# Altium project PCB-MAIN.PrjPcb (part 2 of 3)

## Sheet PCB-MAIN_03_AUDIO.SchDoc
size 594 x 420 mm
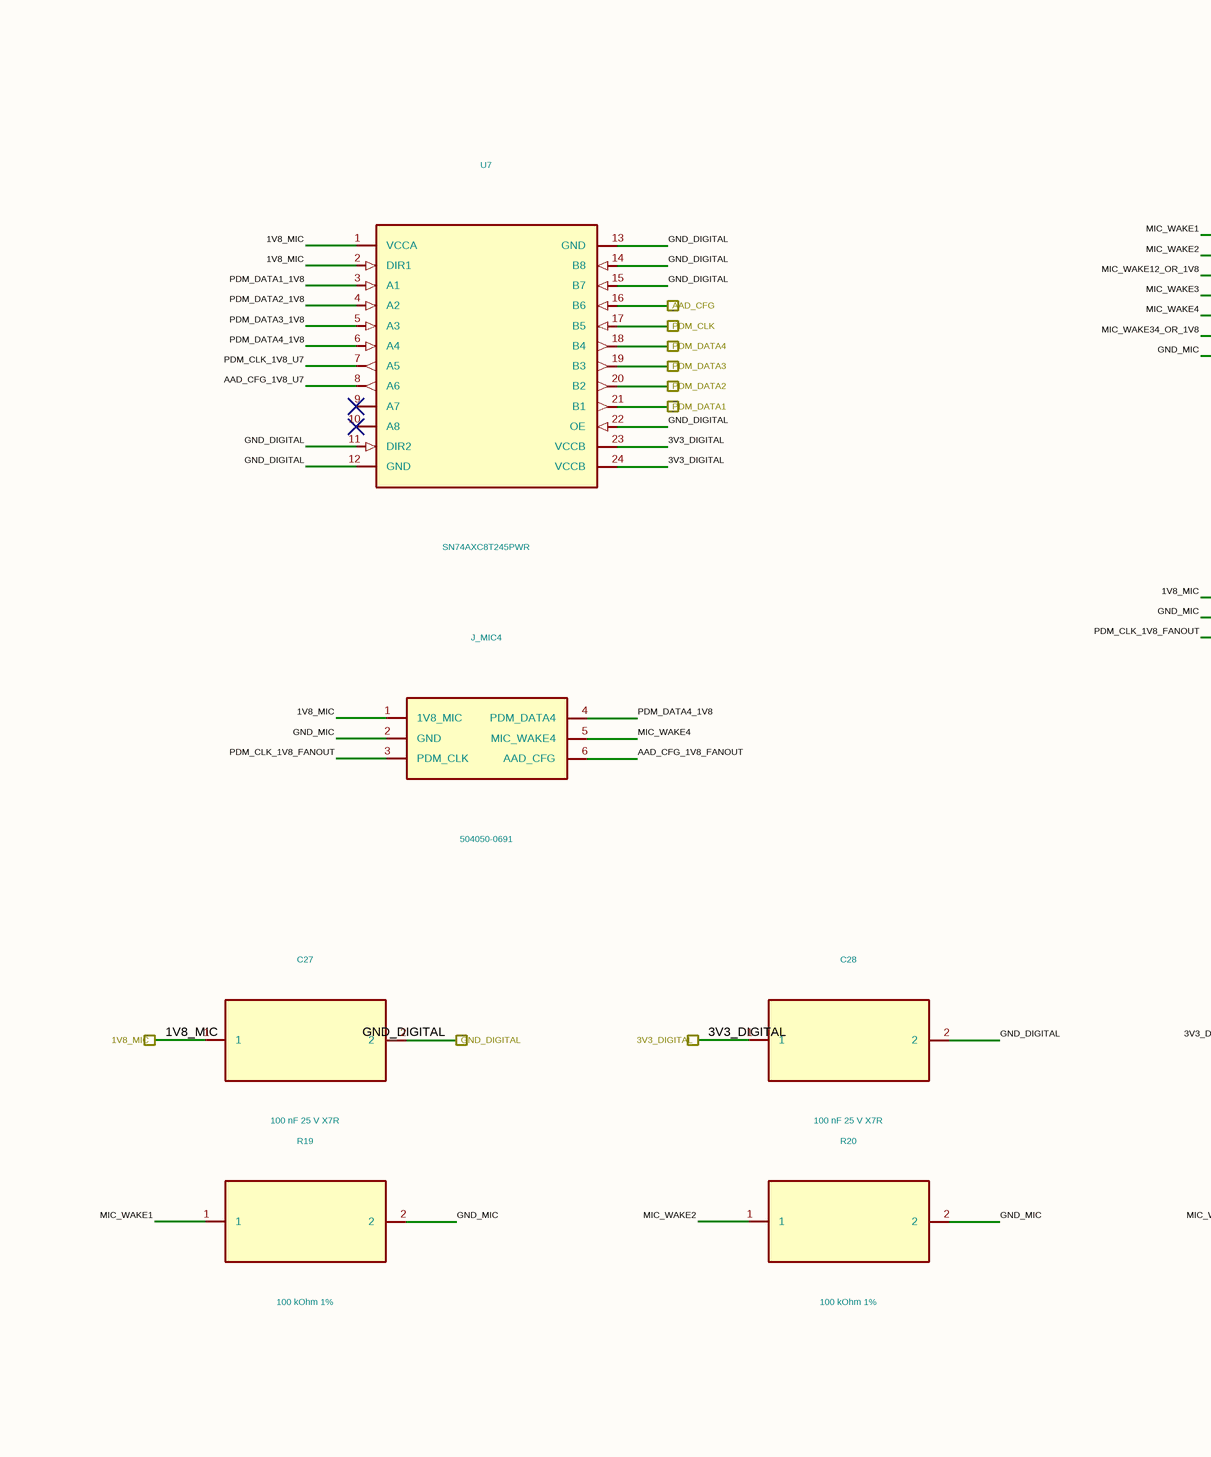
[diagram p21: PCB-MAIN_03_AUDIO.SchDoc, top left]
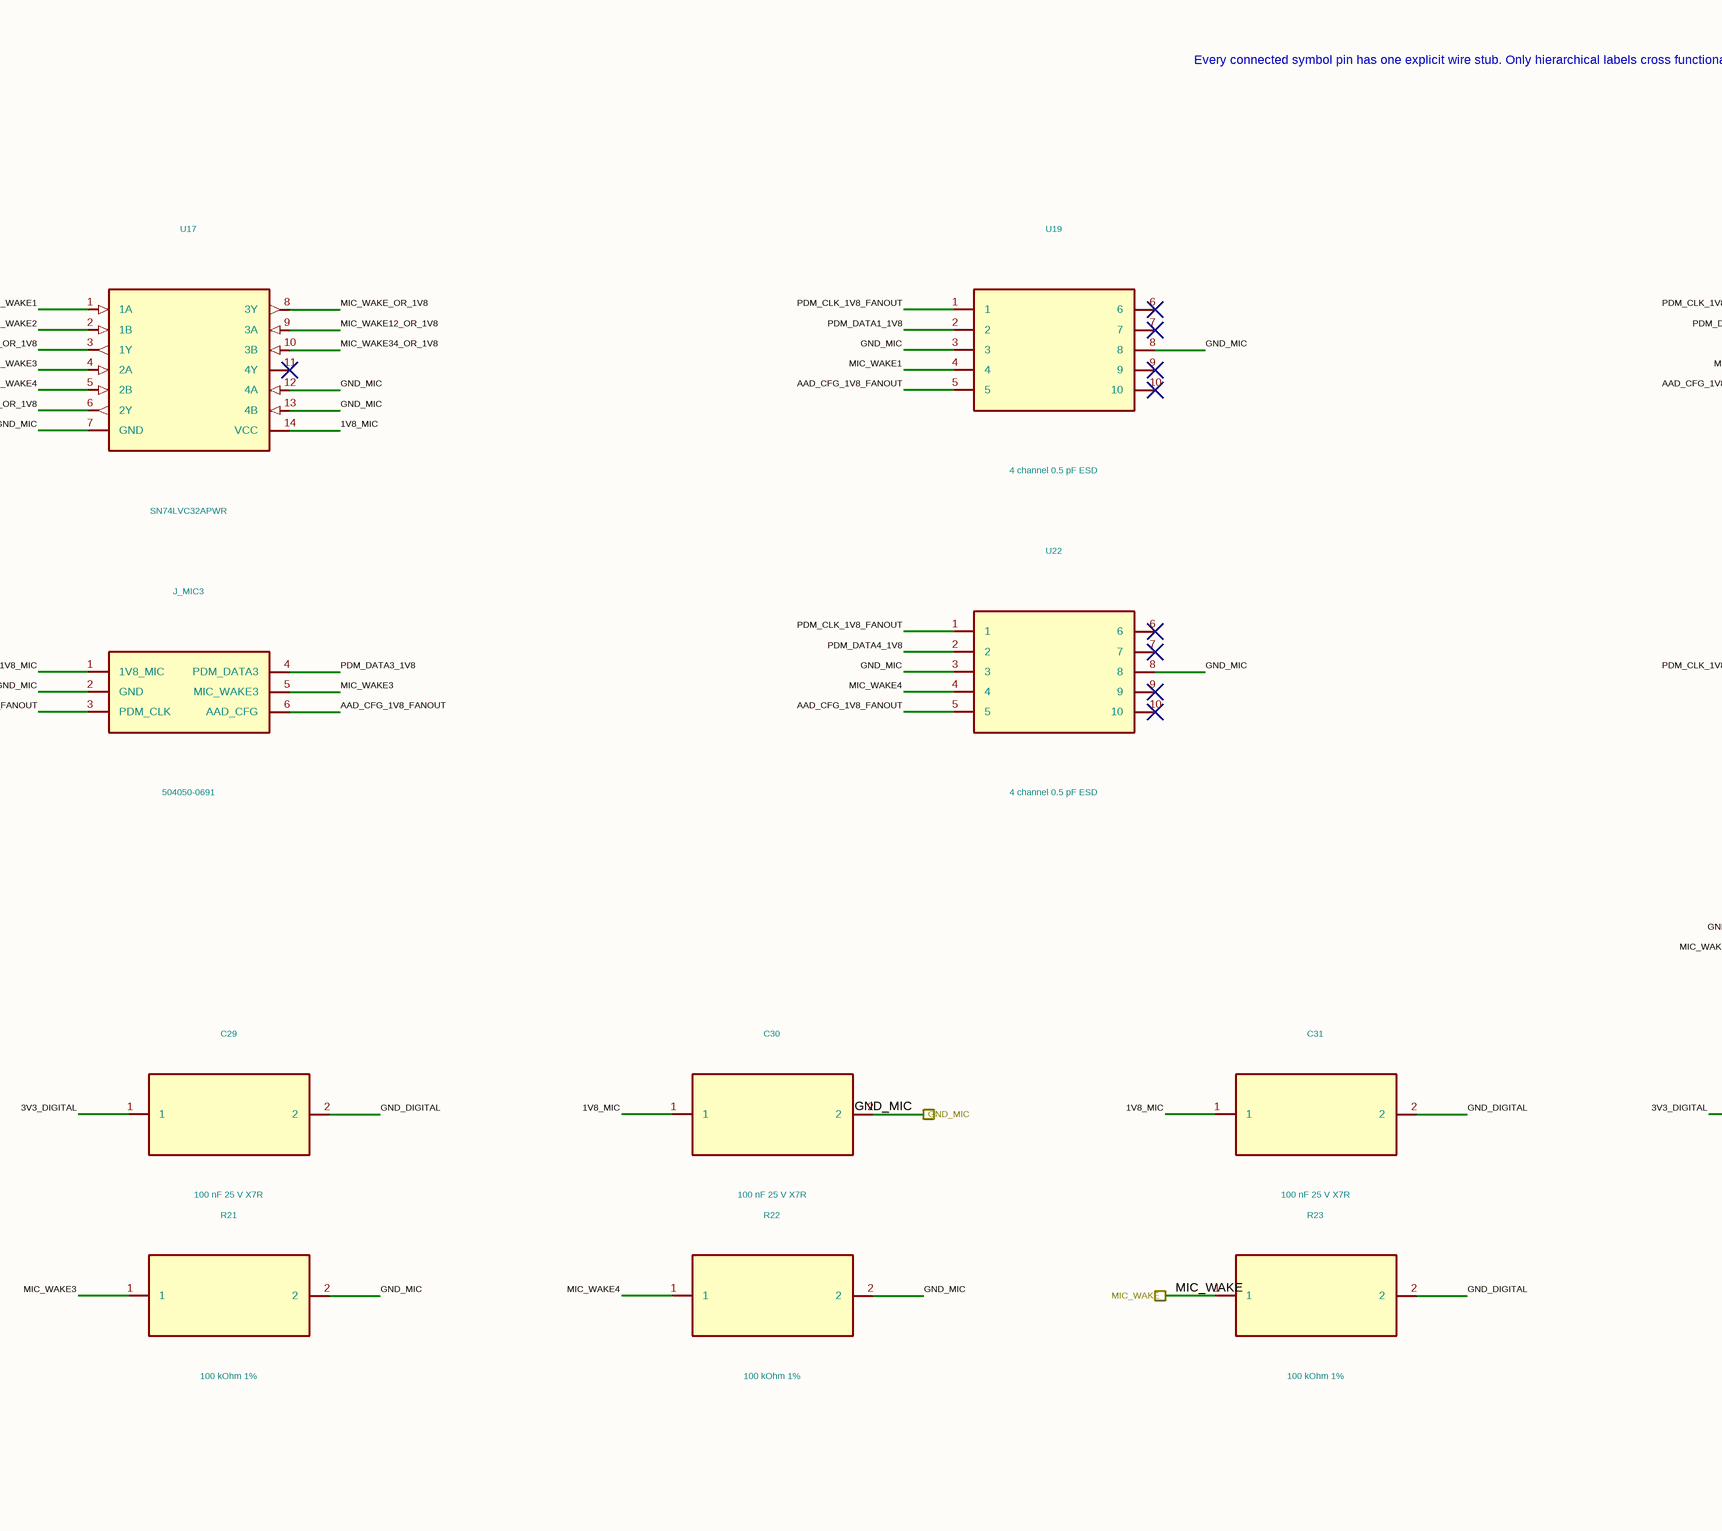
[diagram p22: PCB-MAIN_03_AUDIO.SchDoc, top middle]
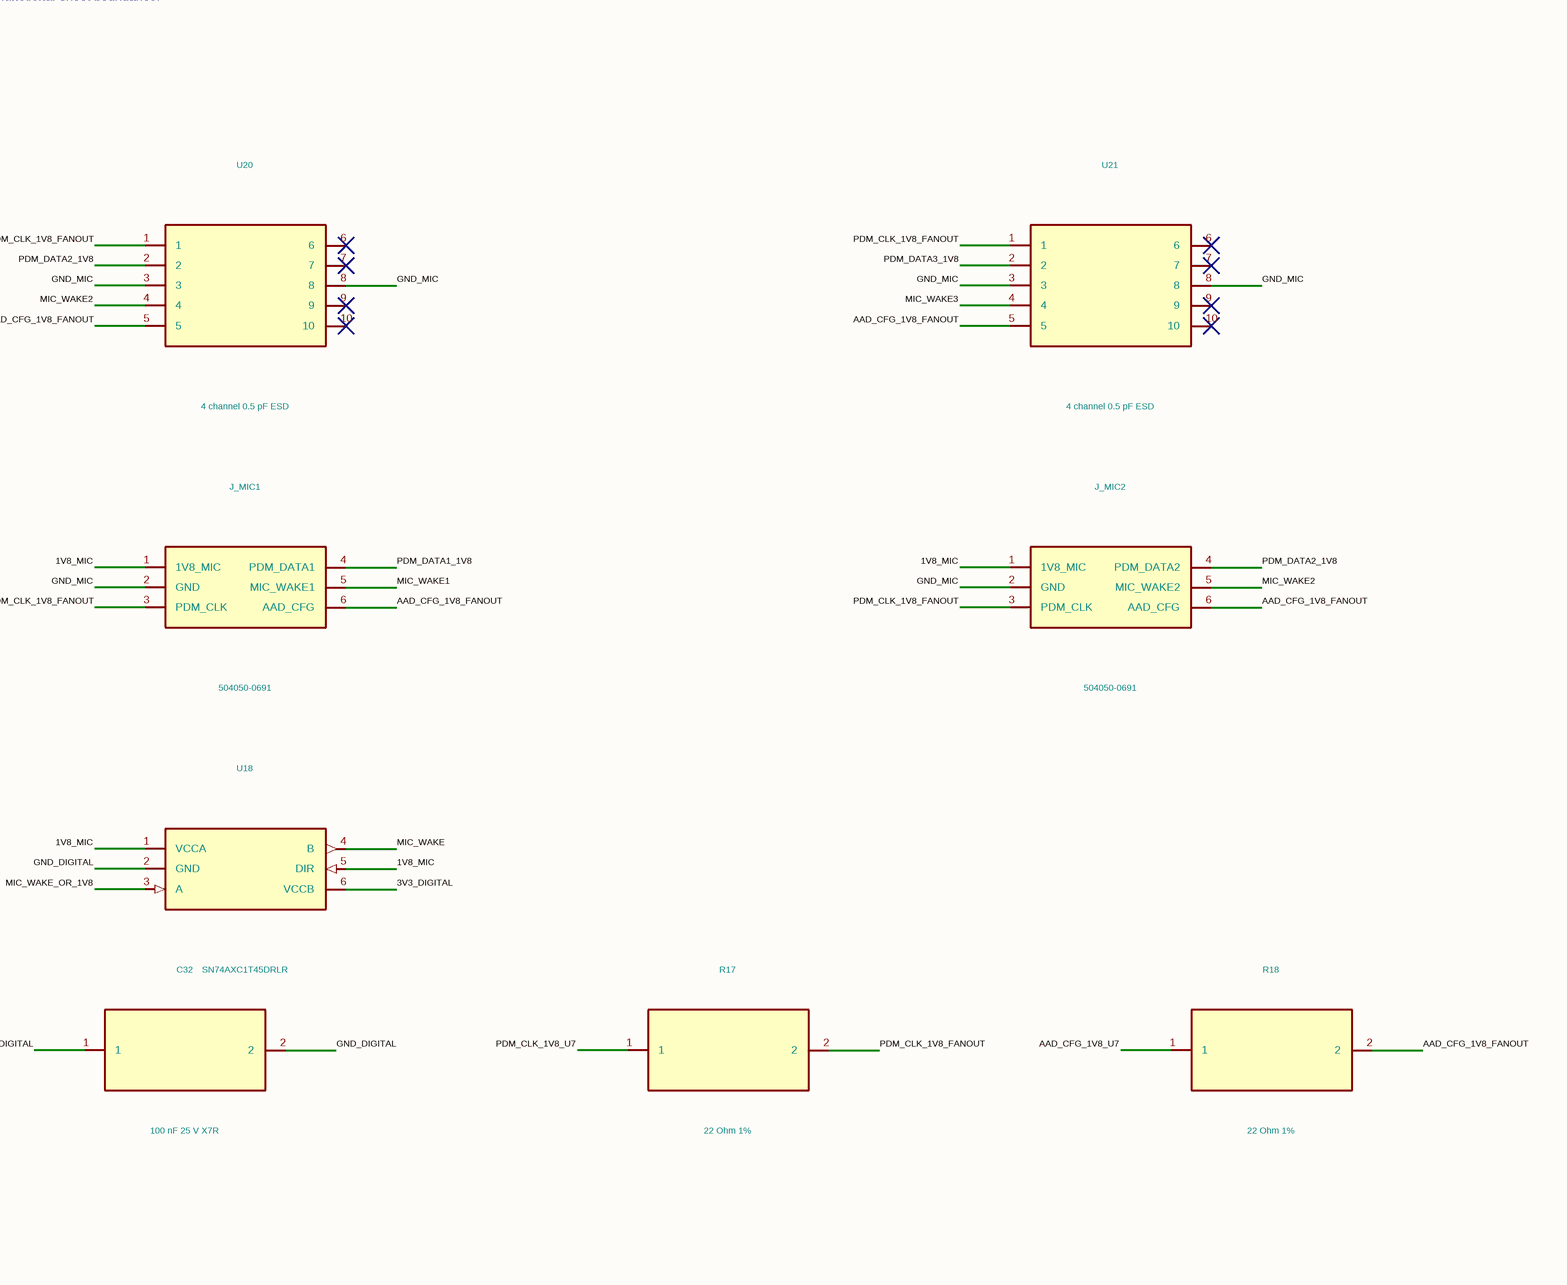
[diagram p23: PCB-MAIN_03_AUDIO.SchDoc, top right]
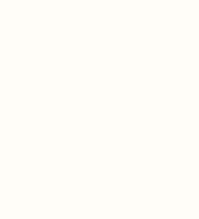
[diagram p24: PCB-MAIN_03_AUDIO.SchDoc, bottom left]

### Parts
C27  100 nF 25 V X7R  [C_0402_1005Metric]
C28  100 nF 25 V X7R  [C_0402_1005Metric]
C29  100 nF 25 V X7R  [C_0402_1005Metric]
C30  100 nF 25 V X7R  [C_0402_1005Metric]
C31  100 nF 25 V X7R  [C_0402_1005Metric]
C32  100 nF 25 V X7R  [C_0402_1005Metric]
J_MIC1  504050-0691
J_MIC2  504050-0691
J_MIC3  504050-0691
J_MIC4  504050-0691
R17  22 Ohm 1%  [R_0402_1005Metric]
R18  22 Ohm 1%  [R_0402_1005Metric]
R19  100 kOhm 1%  [R_0402_1005Metric]
R20  100 kOhm 1%  [R_0402_1005Metric]
R21  100 kOhm 1%  [R_0402_1005Metric]
R22  100 kOhm 1%  [R_0402_1005Metric]
R23  100 kOhm 1%  [R_0402_1005Metric]
U7  SN74AXC8T245PWR
U17  SN74LVC32APWR
U18  SN74AXC1T45DRLR
U19  4 channel 0.5 pF ESD
U20  4 channel 0.5 pF ESD
U21  4 channel 0.5 pF ESD
U22  4 channel 0.5 pF ESD

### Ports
1V8_MIC, 3V3_DIGITAL, AAD_CFG, GND_DIGITAL, GND_MIC, MIC_WAKE, PDM_CLK, PDM_DATA1, PDM_DATA2, PDM_DATA3, PDM_DATA4

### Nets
1V8_MIC: C27.1 C30.1 C31.1 J_MIC1.1(1V8_MIC) J_MIC2.1(1V8_MIC) J_MIC3.1(1V8_MIC) J_MIC4.1(1V8_MIC) U7.1(VCCA) U7.2(DIR1) U17.14(VCC) U18.1(VCCA) U18.5(DIR) ; port 1V8_MIC
3V3_DIGITAL: C28.1 C29.1 C32.1 U7.23(VCCB) U7.24(VCCB) U18.6(VCCB) ; port 3V3_DIGITAL
AAD_CFG: U7.16(B6) ; port AAD_CFG
AAD_CFG_1V8_FANOUT: J_MIC1.6(AAD_CFG) J_MIC2.6(AAD_CFG) J_MIC3.6(AAD_CFG) J_MIC4.6(AAD_CFG) R18.2 U19.5 U20.5 U21.5 U22.5
AAD_CFG_1V8_U7: R18.1 U7.8(A6)
GND_DIGITAL: C27.2 C28.2 C29.2 C31.2 C32.2 R23.2 U7.11(DIR2) U7.12(GND) U7.13(GND) U7.14(B8) U7.15(B7) U7.22(OE) U18.2(GND) ; port GND_DIGITAL
GND_MIC: C30.2 J_MIC1.2(GND) J_MIC2.2(GND) J_MIC3.2(GND) J_MIC4.2(GND) R19.2 R20.2 R21.2 R22.2 U17.7(GND) U17.12(4A) U17.13(4B) U19.3 U19.8 U20.3 U20.8 U21.3 U21.8 U22.3 U22.8 ; port GND_MIC
MIC_WAKE: R23.1 U18.4(B) ; port MIC_WAKE
MIC_WAKE1: J_MIC1.5(MIC_WAKE1) R19.1 U17.1(1A) U19.4
MIC_WAKE2: J_MIC2.5(MIC_WAKE2) R20.1 U17.2(1B) U20.4
MIC_WAKE3: J_MIC3.5(MIC_WAKE3) R21.1 U17.4(2A) U21.4
MIC_WAKE4: J_MIC4.5(MIC_WAKE4) R22.1 U17.5(2B) U22.4
MIC_WAKE12_OR_1V8: U17.3(1Y) U17.9(3A)
MIC_WAKE34_OR_1V8: U17.6(2Y) U17.10(3B)
MIC_WAKE_OR_1V8: U17.8(3Y) U18.3(A)
PDM_CLK: U7.17(B5) ; port PDM_CLK
PDM_CLK_1V8_FANOUT: J_MIC1.3(PDM_CLK) J_MIC2.3(PDM_CLK) J_MIC3.3(PDM_CLK) J_MIC4.3(PDM_CLK) R17.2 U19.1 U20.1 U21.1 U22.1
PDM_CLK_1V8_U7: R17.1 U7.7(A5)
PDM_DATA1: U7.21(B1) ; port PDM_DATA1
PDM_DATA1_1V8: J_MIC1.4(PDM_DATA1) U7.3(A1) U19.2
PDM_DATA2: U7.20(B2) ; port PDM_DATA2
PDM_DATA2_1V8: J_MIC2.4(PDM_DATA2) U7.4(A2) U20.2
PDM_DATA3: U7.19(B3) ; port PDM_DATA3
PDM_DATA3_1V8: J_MIC3.4(PDM_DATA3) U7.5(A3) U21.2
PDM_DATA4: U7.18(B4) ; port PDM_DATA4
PDM_DATA4_1V8: J_MIC4.4(PDM_DATA4) U7.6(A4) U22.2

Not connected (* = marked no-connect by the designer): U7 9(A7)* 10(A8)*; U17 11(4Y)*; U19 6* 7* 9* 10*; U20 6* 7* 9* 10*; U21 6* 7* 9* 10*; U22 6* 7* 9* 10*

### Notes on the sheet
- Every connected symbol pin has one explicit wire stub. Only hierarchical labels cross functional-sheet boundaries.

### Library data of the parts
C27 = C27_GRM155R71E104KE14D: Manufacturer: Murata; Population: FITTED; Authority: TI_SCES875C_RevC
C28 = C28_GRM155R71E104KE14D: Manufacturer: Murata; Population: FITTED; Authority: TI_SCES875C_RevC
C29 = C29_GRM155R71E104KE14D: Manufacturer: Murata; Population: FITTED; Authority: TI_SCES875C_RevC
C30 = C30_GRM155R71E104KE14D: Manufacturer: Murata; Population: FITTED; Authority: TI_SCAS286U_RevU
C31 = C31_GRM155R71E104KE14D: Manufacturer: Murata; Population: FITTED; Authority: TI_SCES882E_RevE
C32 = C32_GRM155R71E104KE14D: Manufacturer: Murata; Population: FITTED; Authority: TI_SCES882E_RevE
J_MIC1 = J_MIC1_504050-0691: Manufacturer: Molex; Population: FITTED; Authority: HARNESS_LOGICAL_PINOUT_REV_A.csv
J_MIC2 = J_MIC2_504050-0691: Manufacturer: Molex; Population: FITTED; Authority: HARNESS_LOGICAL_PINOUT_REV_A.csv
J_MIC3 = J_MIC3_504050-0691: Manufacturer: Molex; Population: FITTED; Authority: HARNESS_LOGICAL_PINOUT_REV_A.csv
J_MIC4 = J_MIC4_504050-0691: Manufacturer: Molex; Population: FITTED; Authority: HARNESS_LOGICAL_PINOUT_REV_A.csv
R17 = R17_ERJ-2RKF22R0X: Manufacturer: Panasonic; Population: FITTED; Authority: PROJECT_MAIN_AUTH_010
R18 = R18_ERJ-2RKF22R0X: Manufacturer: Panasonic; Population: FITTED; Authority: PROJECT_MAIN_AUTH_010
R19 = R19_ERJ-2RKF1003X: Manufacturer: Panasonic; Population: FITTED; Authority: TDK_T5838_DS-000383_Rev1.2
R20 = R20_ERJ-2RKF1003X: Manufacturer: Panasonic; Population: FITTED; Authority: TDK_T5838_DS-000383_Rev1.2
R21 = R21_ERJ-2RKF1003X: Manufacturer: Panasonic; Population: FITTED; Authority: TDK_T5838_DS-000383_Rev1.2
R22 = R22_ERJ-2RKF1003X: Manufacturer: Panasonic; Population: FITTED; Authority: TDK_T5838_DS-000383_Rev1.2
R23 = R23_ERJ-2RKF1003X: Manufacturer: Panasonic; Population: FITTED; Authority: TI_SCES882E_RevE
U7 = U7_SN74AXC8T245PWR: Manufacturer: Texas Instruments; Population: FITTED; Authority: PCB_MAIN_AUDIO_LOGIC_PIN_AUTHORITY_REV_A.csv
U17 = U17_SN74LVC32APWR: Manufacturer: Texas Instruments; Population: FITTED; Authority: PCB_MAIN_AUDIO_LOGIC_PIN_AUTHORITY_REV_A.csv
U18 = U18_SN74AXC1T45DRLR: Manufacturer: Texas Instruments; Population: FITTED; Authority: PCB_MAIN_AUDIO_LOGIC_PIN_AUTHORITY_REV_A.csv
U19 = U19_TPD4E05U06DQAR: Manufacturer: Texas Instruments; Population: FITTED; Authority: TI_TPDxE05U06_RevO
U20 = U20_TPD4E05U06DQAR: Manufacturer: Texas Instruments; Population: FITTED; Authority: TI_TPDxE05U06_RevO
U21 = U21_TPD4E05U06DQAR: Manufacturer: Texas Instruments; Population: FITTED; Authority: TI_TPDxE05U06_RevO
U22 = U22_TPD4E05U06DQAR: Manufacturer: Texas Instruments; Population: FITTED; Authority: TI_TPDxE05U06_RevO

## Sheet PCB-MAIN_04_GNSS.SchDoc
size 594 x 420 mm
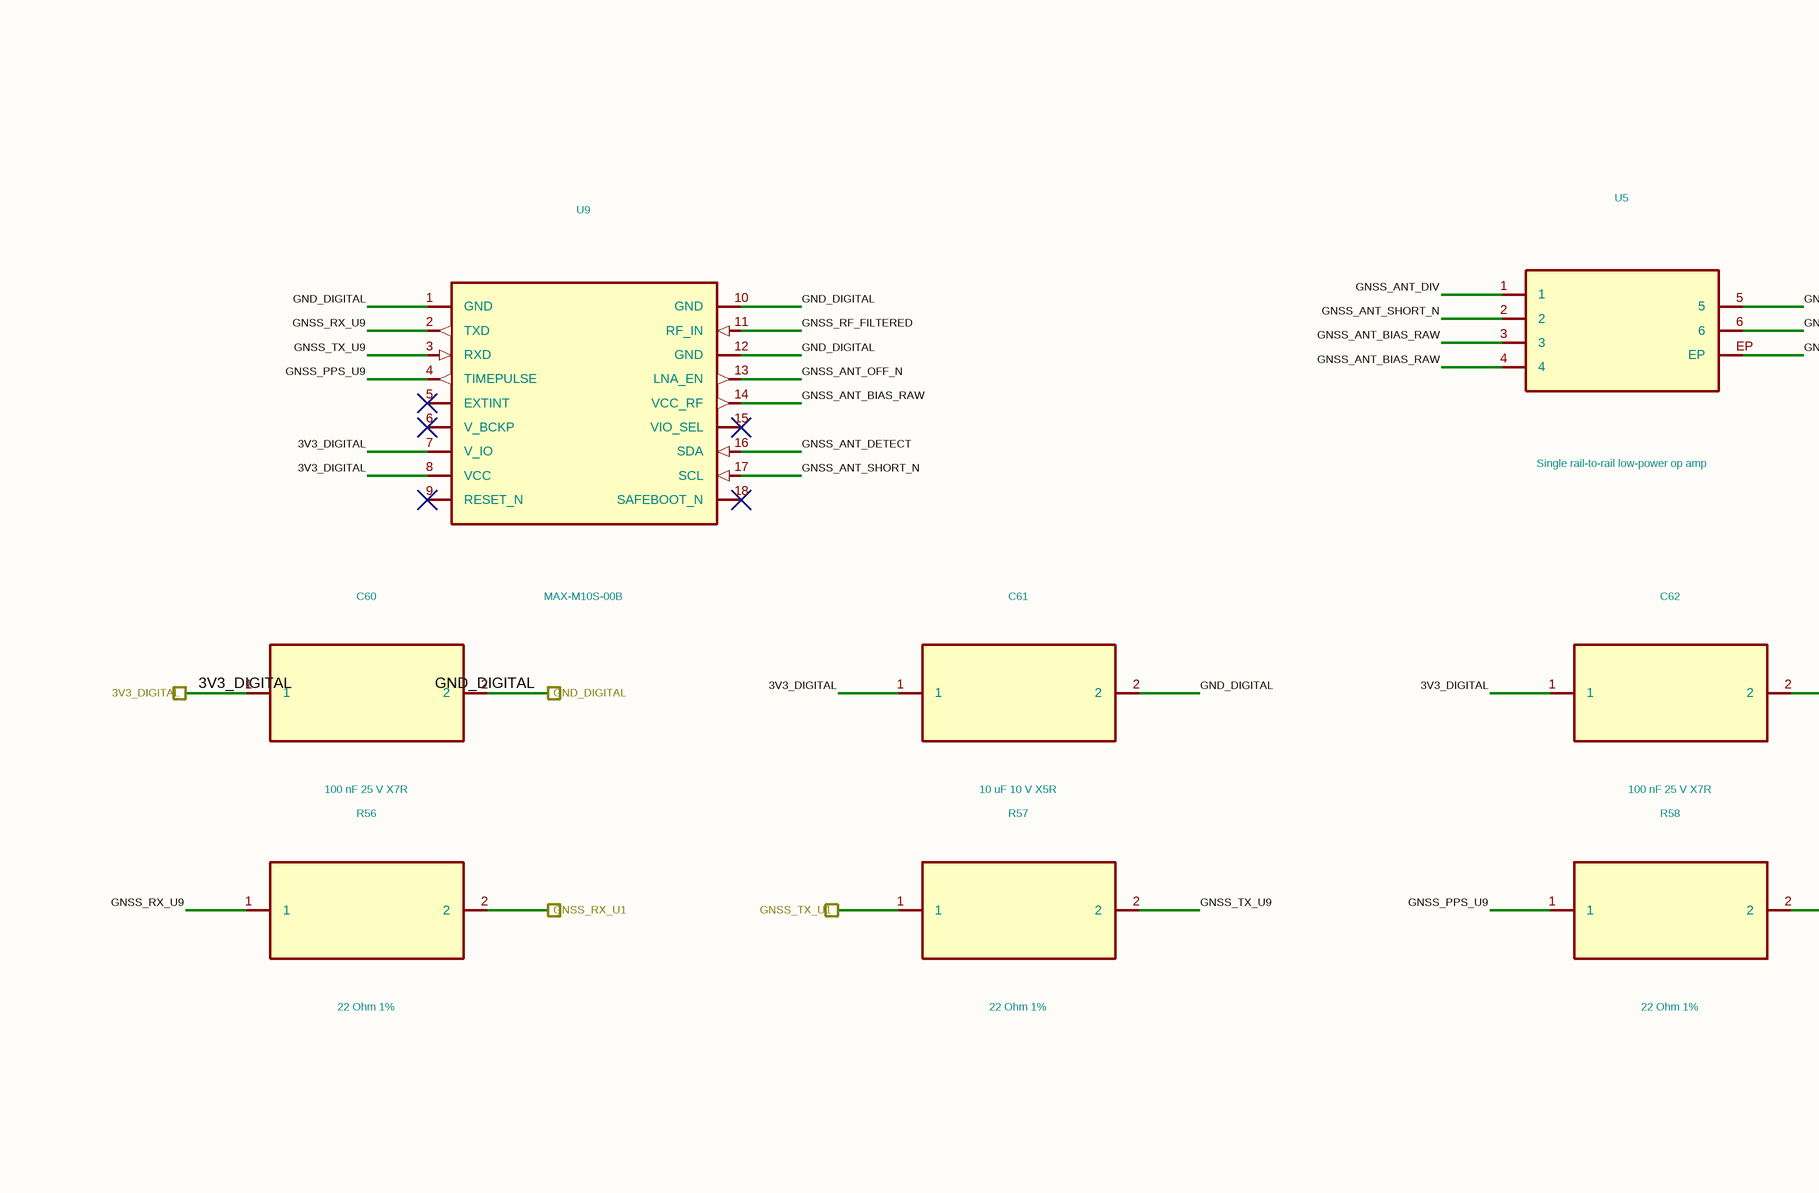
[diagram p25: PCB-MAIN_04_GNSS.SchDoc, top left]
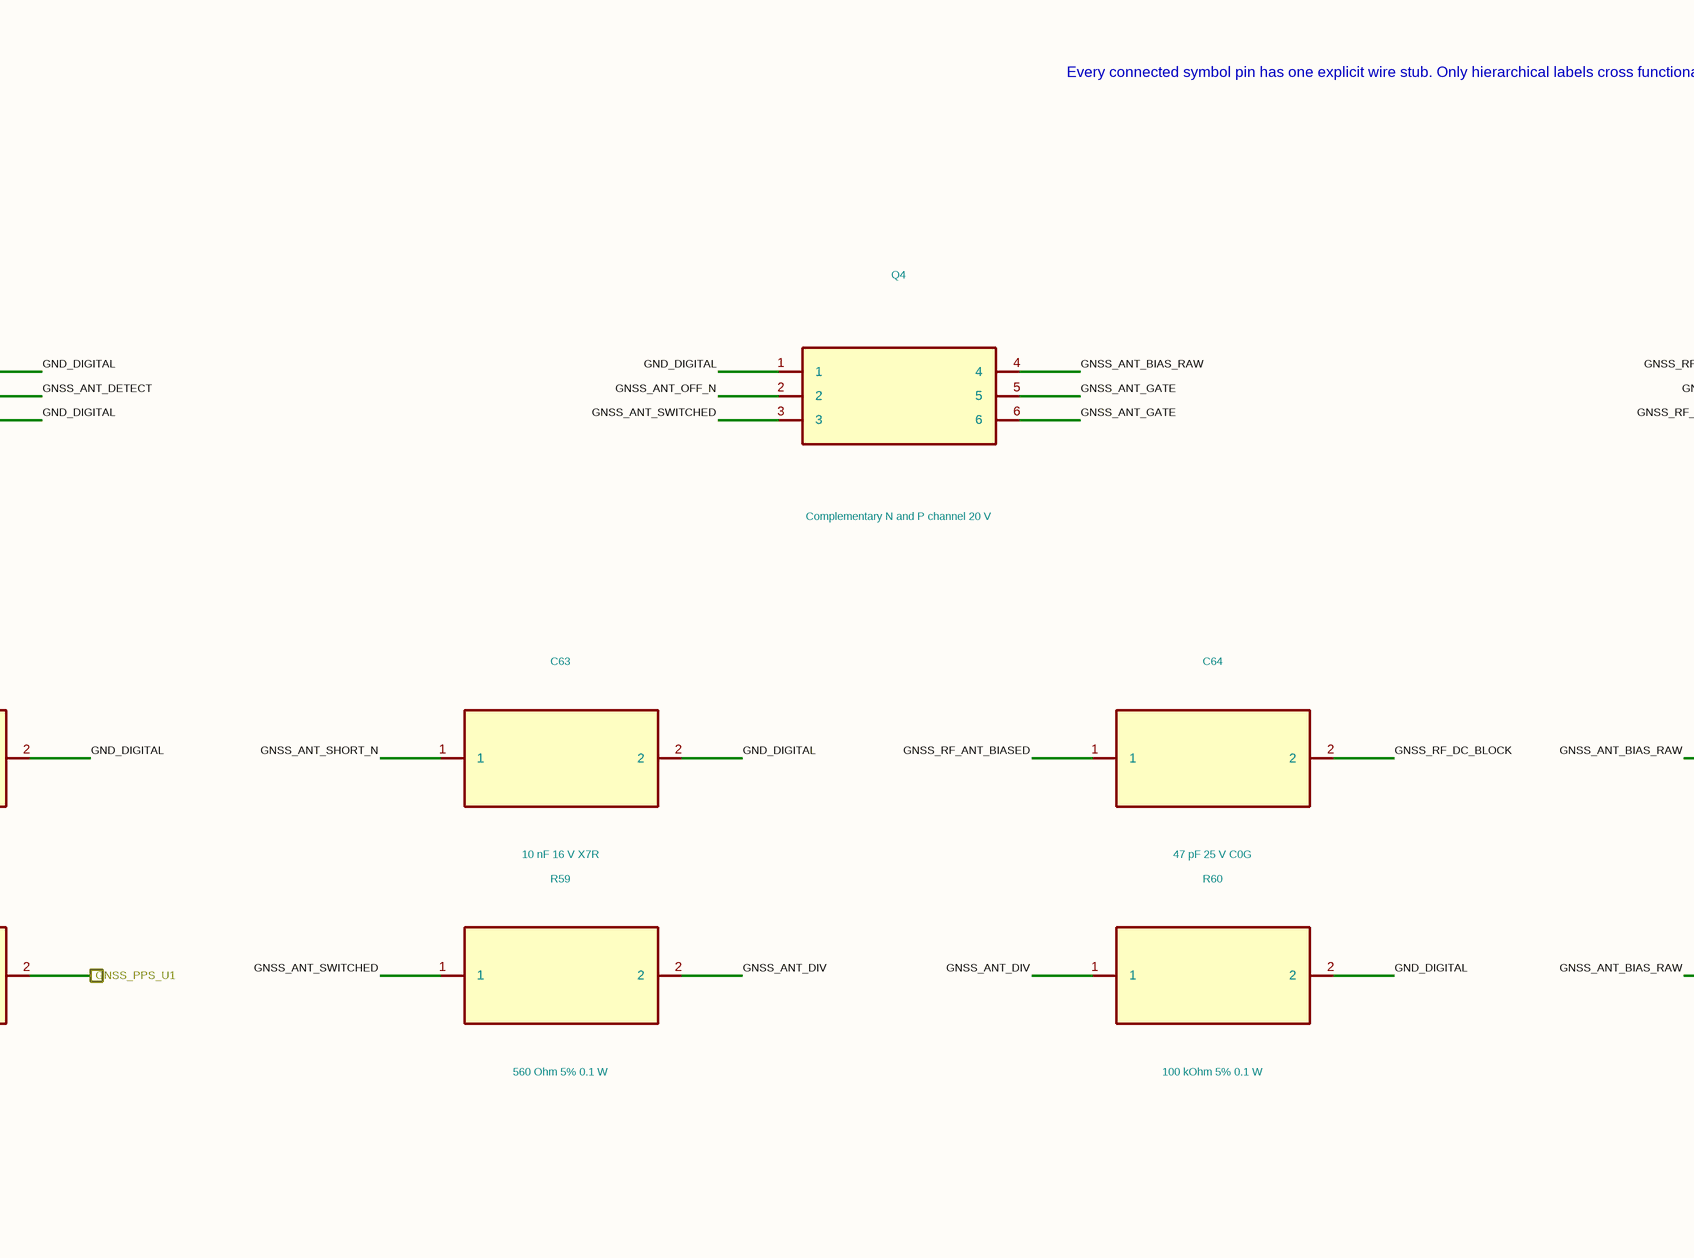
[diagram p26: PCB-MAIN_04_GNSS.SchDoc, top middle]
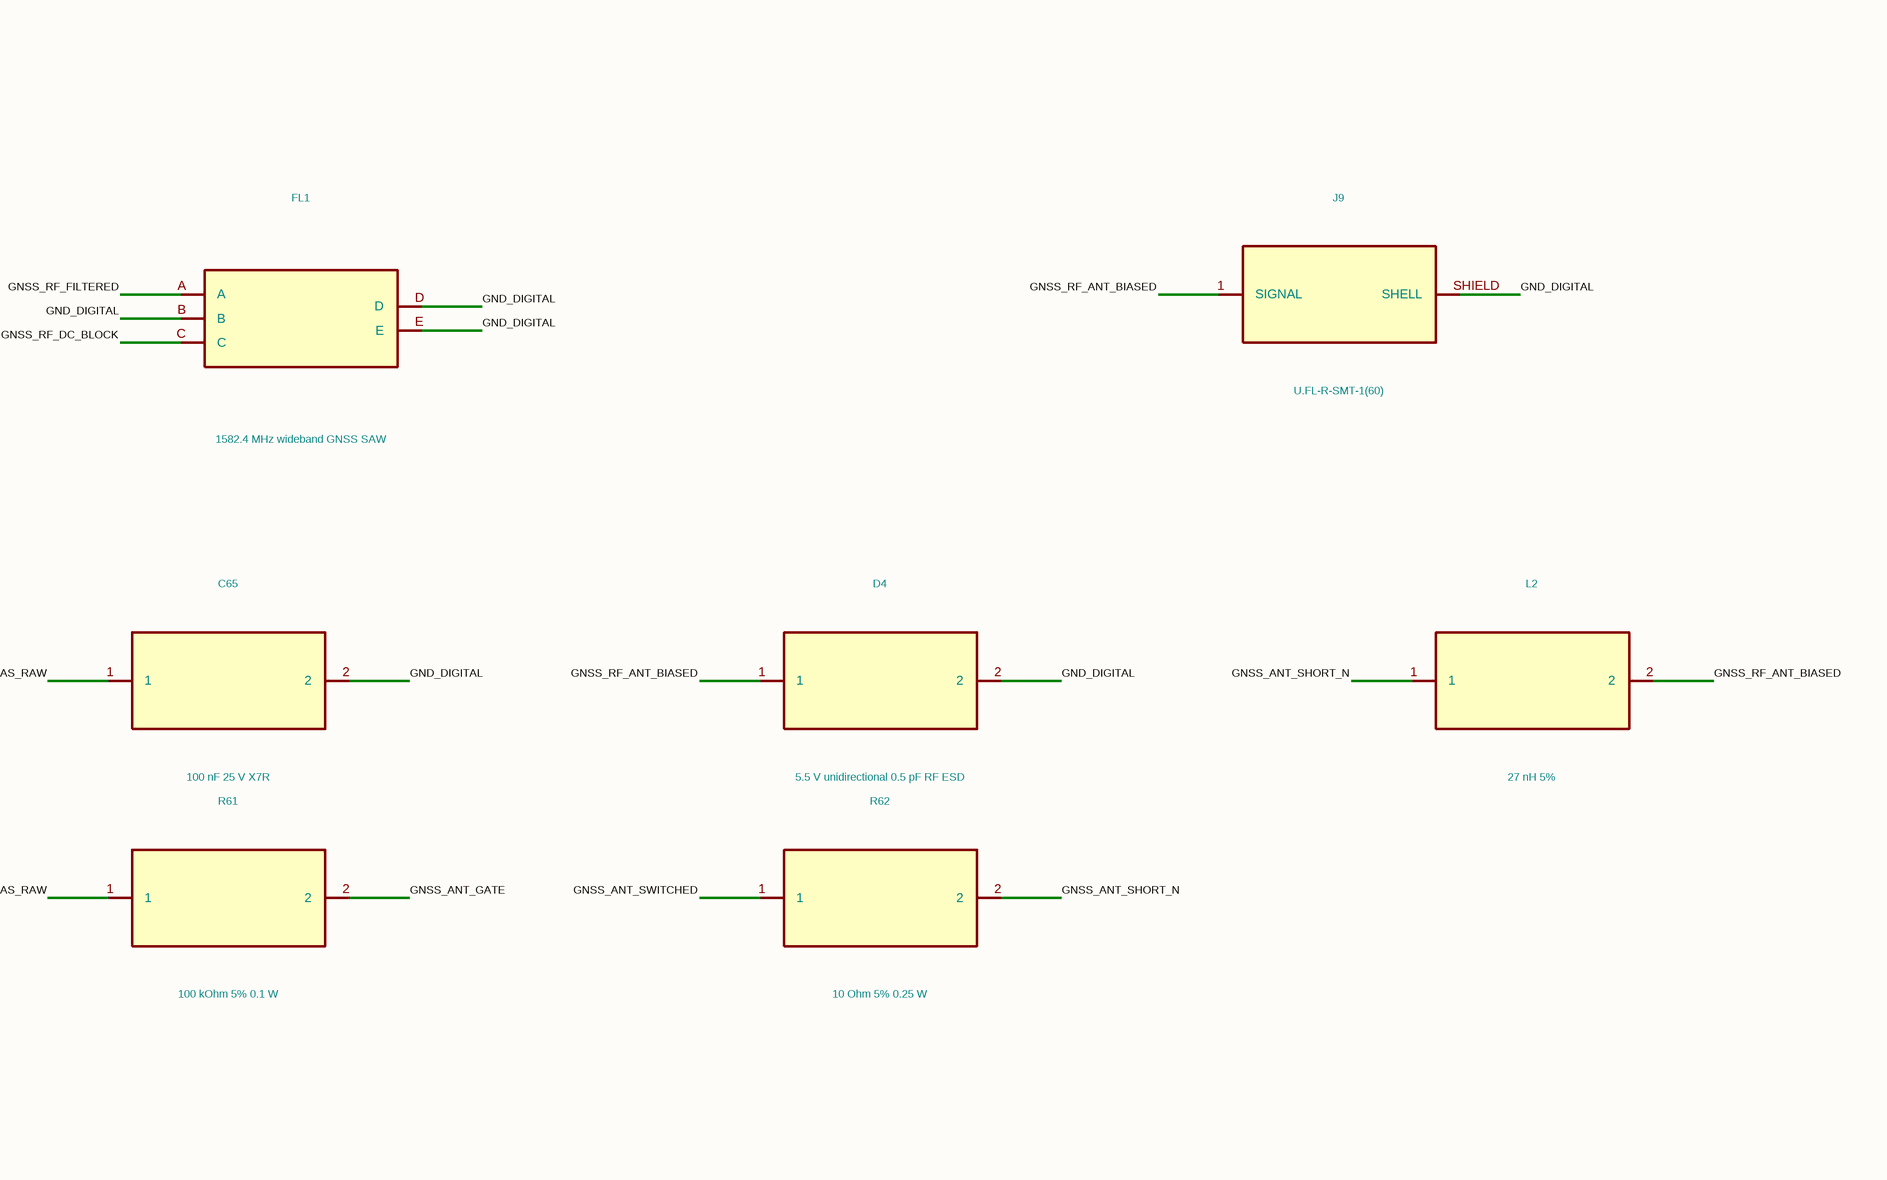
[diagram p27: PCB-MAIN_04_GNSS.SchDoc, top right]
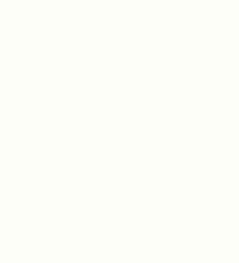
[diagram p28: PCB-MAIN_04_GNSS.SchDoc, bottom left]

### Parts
C60  100 nF 25 V X7R  [C_0402_1005Metric]
C61  10 uF 10 V X5R  [C_0603_1608Metric]
C62  100 nF 25 V X7R  [C_0402_1005Metric]
C63  10 nF 16 V X7R  [C_0402_1005Metric]
C64  47 pF 25 V C0G  [C_0402_1005Metric]
C65  100 nF 25 V X7R  [C_0402_1005Metric]
D4  5.5 V unidirectional 0.5 pF RF ESD
FL1  1582.4 MHz wideband GNSS SAW
J9  U.FL-R-SMT-1(60)
L2  27 nH 5%  [L_0402_1005Metric]
Q4  Complementary N and P channel 20 V
R56  22 Ohm 1%  [R_0402_1005Metric]
R57  22 Ohm 1%  [R_0402_1005Metric]
R58  22 Ohm 1%  [R_0402_1005Metric]
R59  560 Ohm 5% 0.1 W  [R_0402_1005Metric]
R60  100 kOhm 5% 0.1 W  [R_0402_1005Metric]
R61  100 kOhm 5% 0.1 W  [R_0402_1005Metric]
R62  10 Ohm 5% 0.25 W  [R_1206_3216Metric]
U5  Single rail-to-rail low-power op amp
U9  MAX-M10S-00B

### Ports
3V3_DIGITAL, GND_DIGITAL, GNSS_PPS_U1, GNSS_RX_U1, GNSS_TX_U1

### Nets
3V3_DIGITAL: C60.1 C61.1 C62.1 U9.7(V_IO) U9.8(VCC) ; port 3V3_DIGITAL
GND_DIGITAL: C60.2 C61.2 C62.2 C63.2 C65.2 D4.2 FL1.B FL1.D FL1.E J9.SHIELD(SHELL) Q4.1 R60.2 U5.5 U5.EP U9.1(GND) U9.10(GND) U9.12(GND) ; port GND_DIGITAL
GNSS_ANT_BIAS_RAW: C65.1 Q4.4 R61.1 U5.3 U5.4 U9.14(VCC_RF)
GNSS_ANT_DETECT: U5.6 U9.16(SDA)
GNSS_ANT_DIV: R59.2 R60.1 U5.1
GNSS_ANT_GATE: Q4.5 Q4.6 R61.2
GNSS_ANT_OFF_N: Q4.2 U9.13(LNA_EN)
GNSS_ANT_SHORT_N: C63.1 L2.1 R62.2 U5.2 U9.17(SCL)
GNSS_ANT_SWITCHED: Q4.3 R59.1 R62.1
GNSS_PPS_U1: R58.2 ; port GNSS_PPS_U1
GNSS_PPS_U9: R58.1 U9.4(TIMEPULSE)
GNSS_RF_ANT_BIASED: C64.1 D4.1 J9.1(SIGNAL) L2.2
GNSS_RF_DC_BLOCK: C64.2 FL1.C
GNSS_RF_FILTERED: FL1.A U9.11(RF_IN)
GNSS_RX_U1: R56.2 ; port GNSS_RX_U1
GNSS_RX_U9: R56.1 U9.2(TXD)
GNSS_TX_U1: R57.1 ; port GNSS_TX_U1
GNSS_TX_U9: R57.2 U9.3(RXD)

Not connected (* = marked no-connect by the designer): U9 5(EXTINT)* 6(V_BCKP)* 9(RESET_N)* 15(VIO_SEL)* 18(SAFEBOOT_N)*

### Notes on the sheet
- Every connected symbol pin has one explicit wire stub. Only hierarchical labels cross functional-sheet boundaries.

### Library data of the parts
C60 = C60_GRM155R71E104KE14D: Manufacturer: Murata; Population: FITTED; Authority: u-blox_UBX-20053088_R05
C61 = C61_GRM188R61A106KE69D: Manufacturer: Murata; Population: FITTED; Authority: u-blox_UBX-20053088_R05
C62 = C62_GRM155R71E104KE14D: Manufacturer: Murata; Population: FITTED; Authority: u-blox_UBX-20053088_R05
C63 = C63_GRM155R71C103KA01D: Manufacturer: Murata; Population: FITTED; Authority: u-blox_UBX-20053088_R05
C64 = C64_GRM1555C1E470JA01D: Manufacturer: Murata; Population: FITTED; Authority: u-blox_UBX-20053088_R05
C65 = C65_GRM155R71E104KE14D: Manufacturer: Murata; Population: FITTED; Authority: ADI_LT6000_datasheet
D4 = D4_TPD1E05U06DYAR: Manufacturer: Texas Instruments; Population: FITTED; Authority: TI_TPDxE05U06_RevO
FL1 = FL1_ABSES5AF-L100KM: Manufacturer: Abracon; Population: FITTED; Authority: Abracon_ABSES5AF-L100KM_2025-09-16
J9 = J9_U.FL-R-SMT-1_60: Manufacturer: CONTROLLED_AUTHORITY; Population: FITTED; Authority: PCB_MAIN_GNSS_PIN_AUTHORITY_REV_A.csv;PCB_MAIN_CONNECTOR_FIXTURE_PIN_AUTHORITY_REV_A.csv
L2 = L2_LQW15AN27NJ00D: Manufacturer: Murata; Population: FITTED; Authority: u-blox_UBX-20053088_R05
Q4 = Q4_Si1016X-T1-GE3: Manufacturer: Vishay; Population: FITTED; Authority: Vishay_Si1016X_RevE
R56 = R56_ERJ-2RKF22R0X: Manufacturer: Panasonic; Population: FITTED; Authority: u-blox_UBX-20053088_R05
R57 = R57_ERJ-2RKF22R0X: Manufacturer: Panasonic; Population: FITTED; Authority: u-blox_UBX-20053088_R05
R58 = R58_ERJ-2RKF22R0X: Manufacturer: Panasonic; Population: FITTED; Authority: u-blox_UBX-20053088_R05
R59 = R59_ERJ-2GEJ561X: Manufacturer: Panasonic; Population: FITTED; Authority: u-blox_UBX-20053088_R05
R60 = R60_ERJ-2GEJ104X: Manufacturer: Panasonic; Population: FITTED; Authority: u-blox_UBX-20053088_R05
R61 = R61_ERJ-2GEJ104X: Manufacturer: Panasonic; Population: FITTED; Authority: u-blox_UBX-20053088_R05
R62 = R62_ERJ-8GEYJ100V: Manufacturer: Panasonic; Population: FITTED; Authority: u-blox_UBX-20053088_R05
U5 = U5_LT6000IDCB_TRMPBF: Manufacturer: Analog Devices; MPN: LT6000IDCB#TRMPBF; Population: FITTED; Authority: ADI_LT6000_datasheet
U9 = U9_MAX-M10S-00B: Manufacturer: u-blox; Population: FITTED; Authority: PCB_MAIN_GNSS_PIN_AUTHORITY_REV_A.csv

## Sheet PCB-MAIN_05_CELLULAR.SchDoc
size 594 x 420 mm
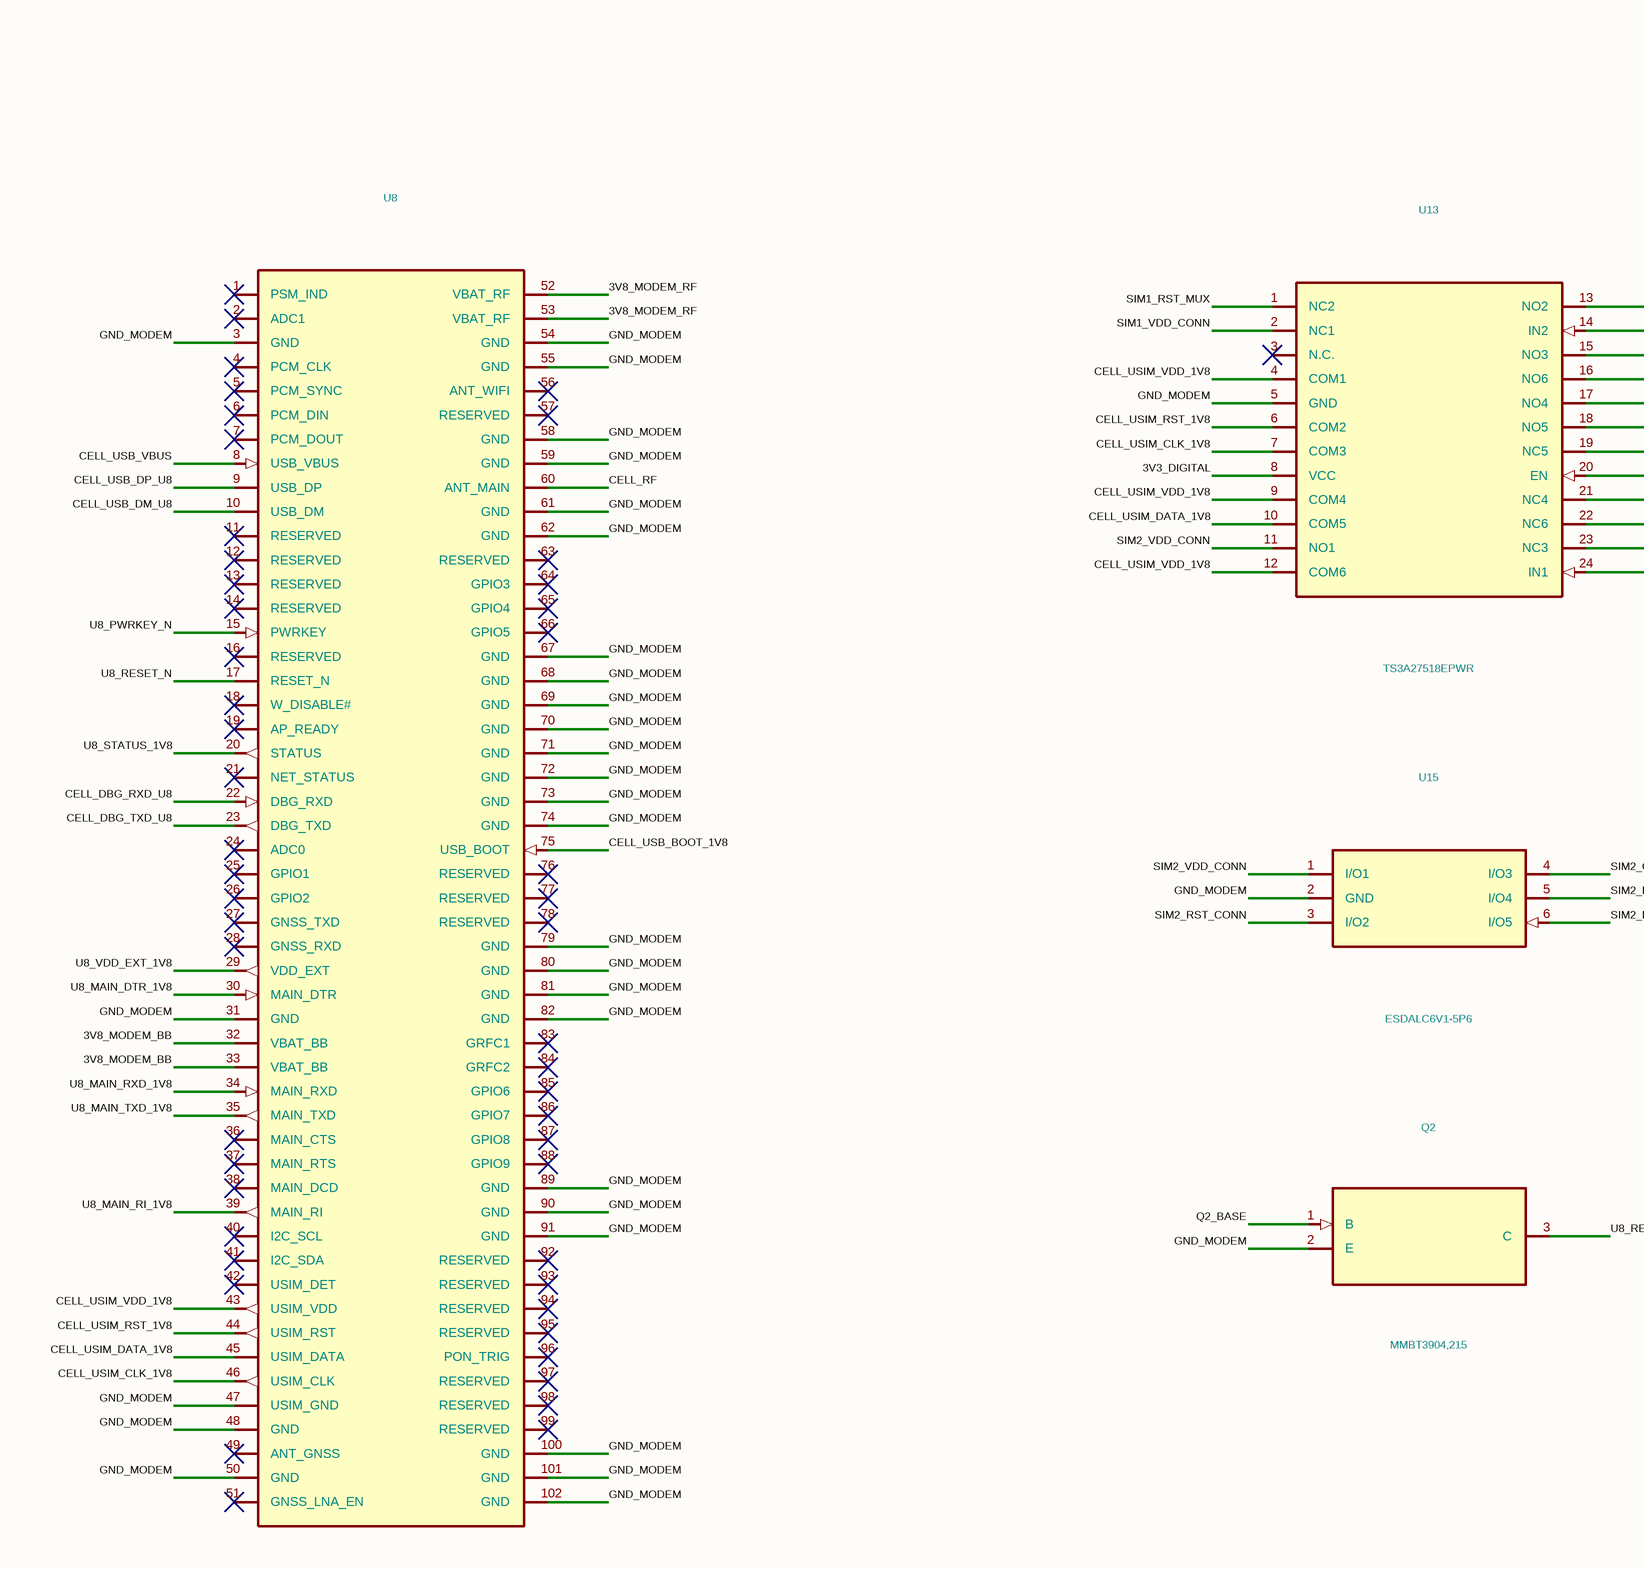
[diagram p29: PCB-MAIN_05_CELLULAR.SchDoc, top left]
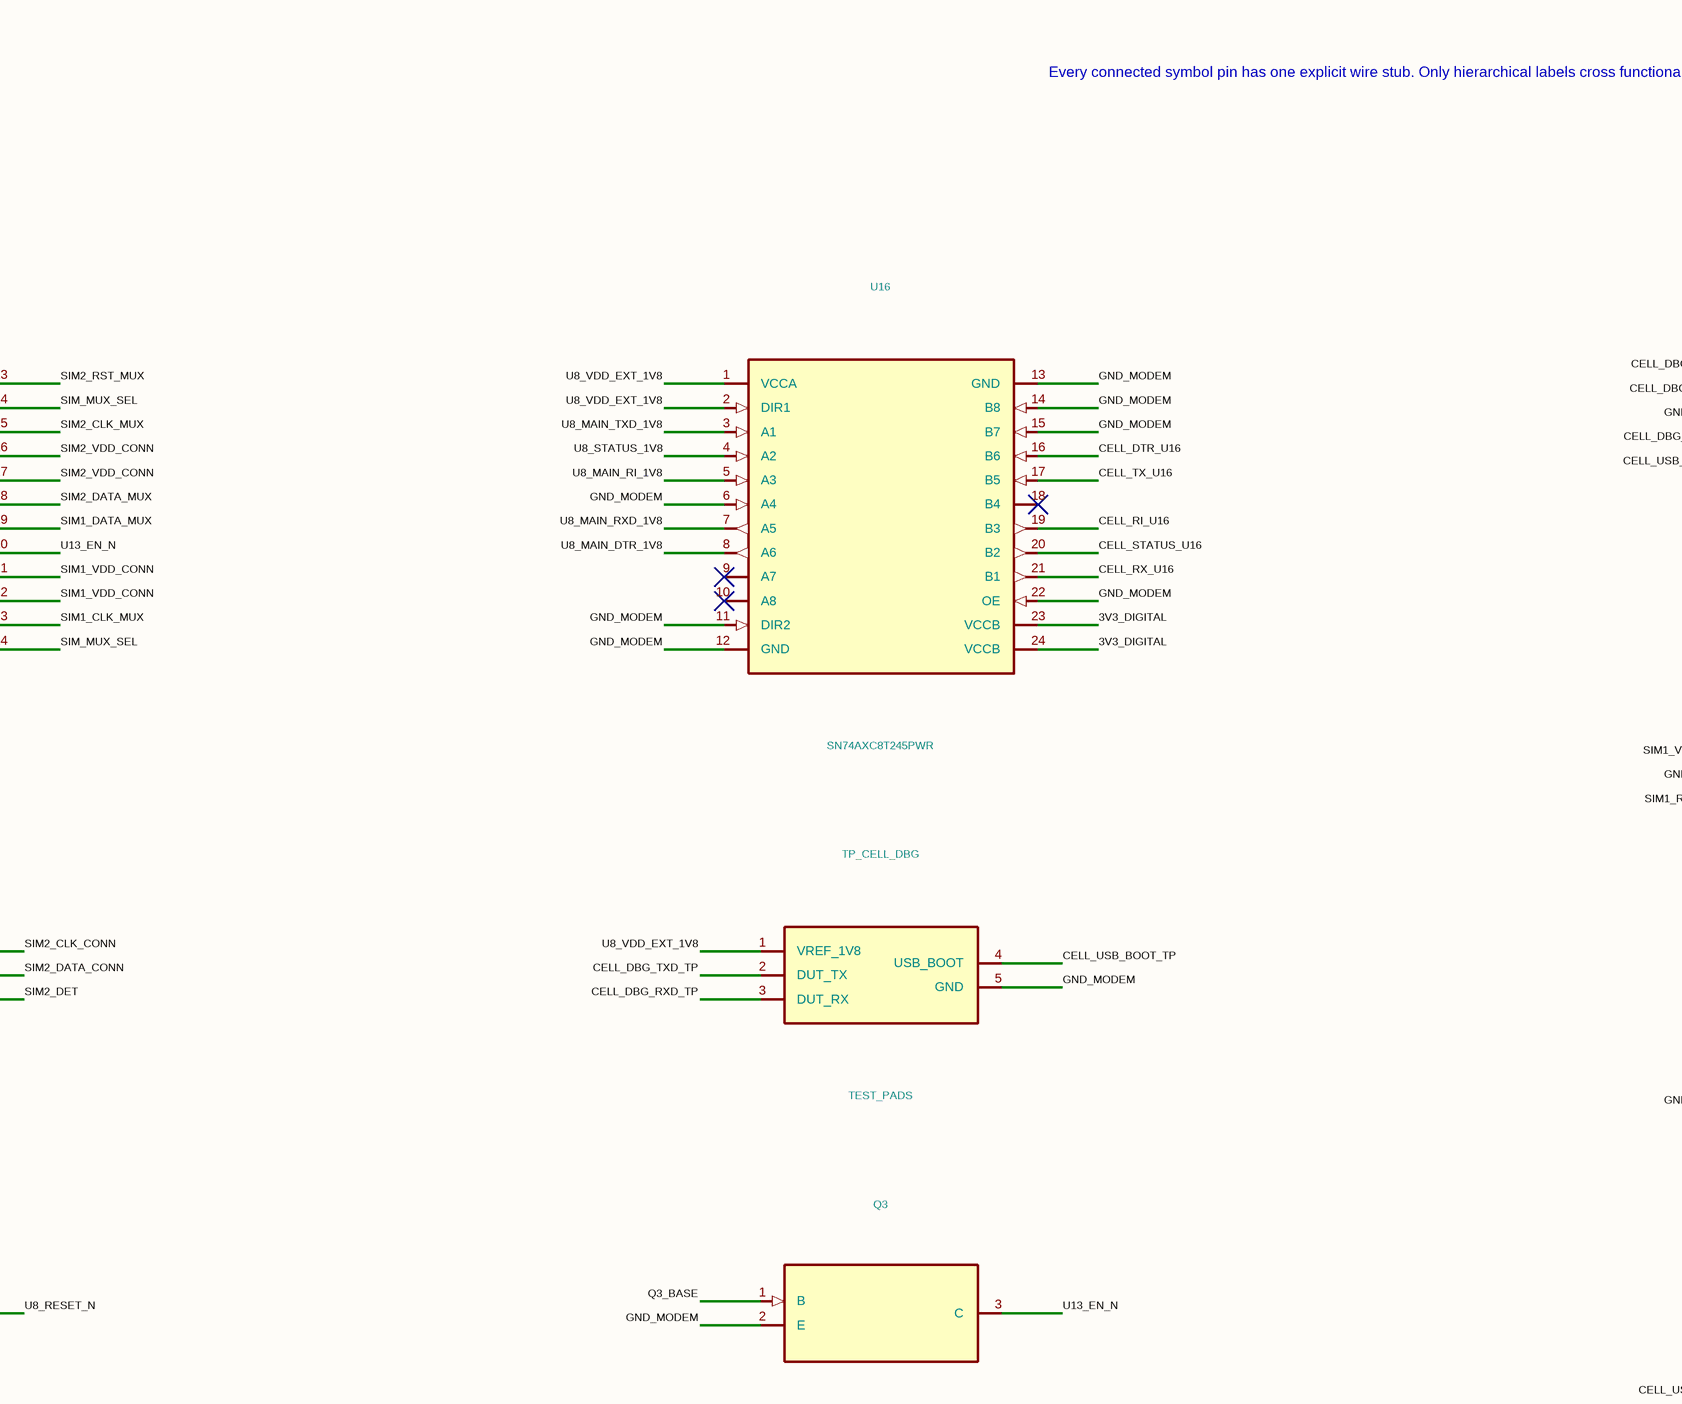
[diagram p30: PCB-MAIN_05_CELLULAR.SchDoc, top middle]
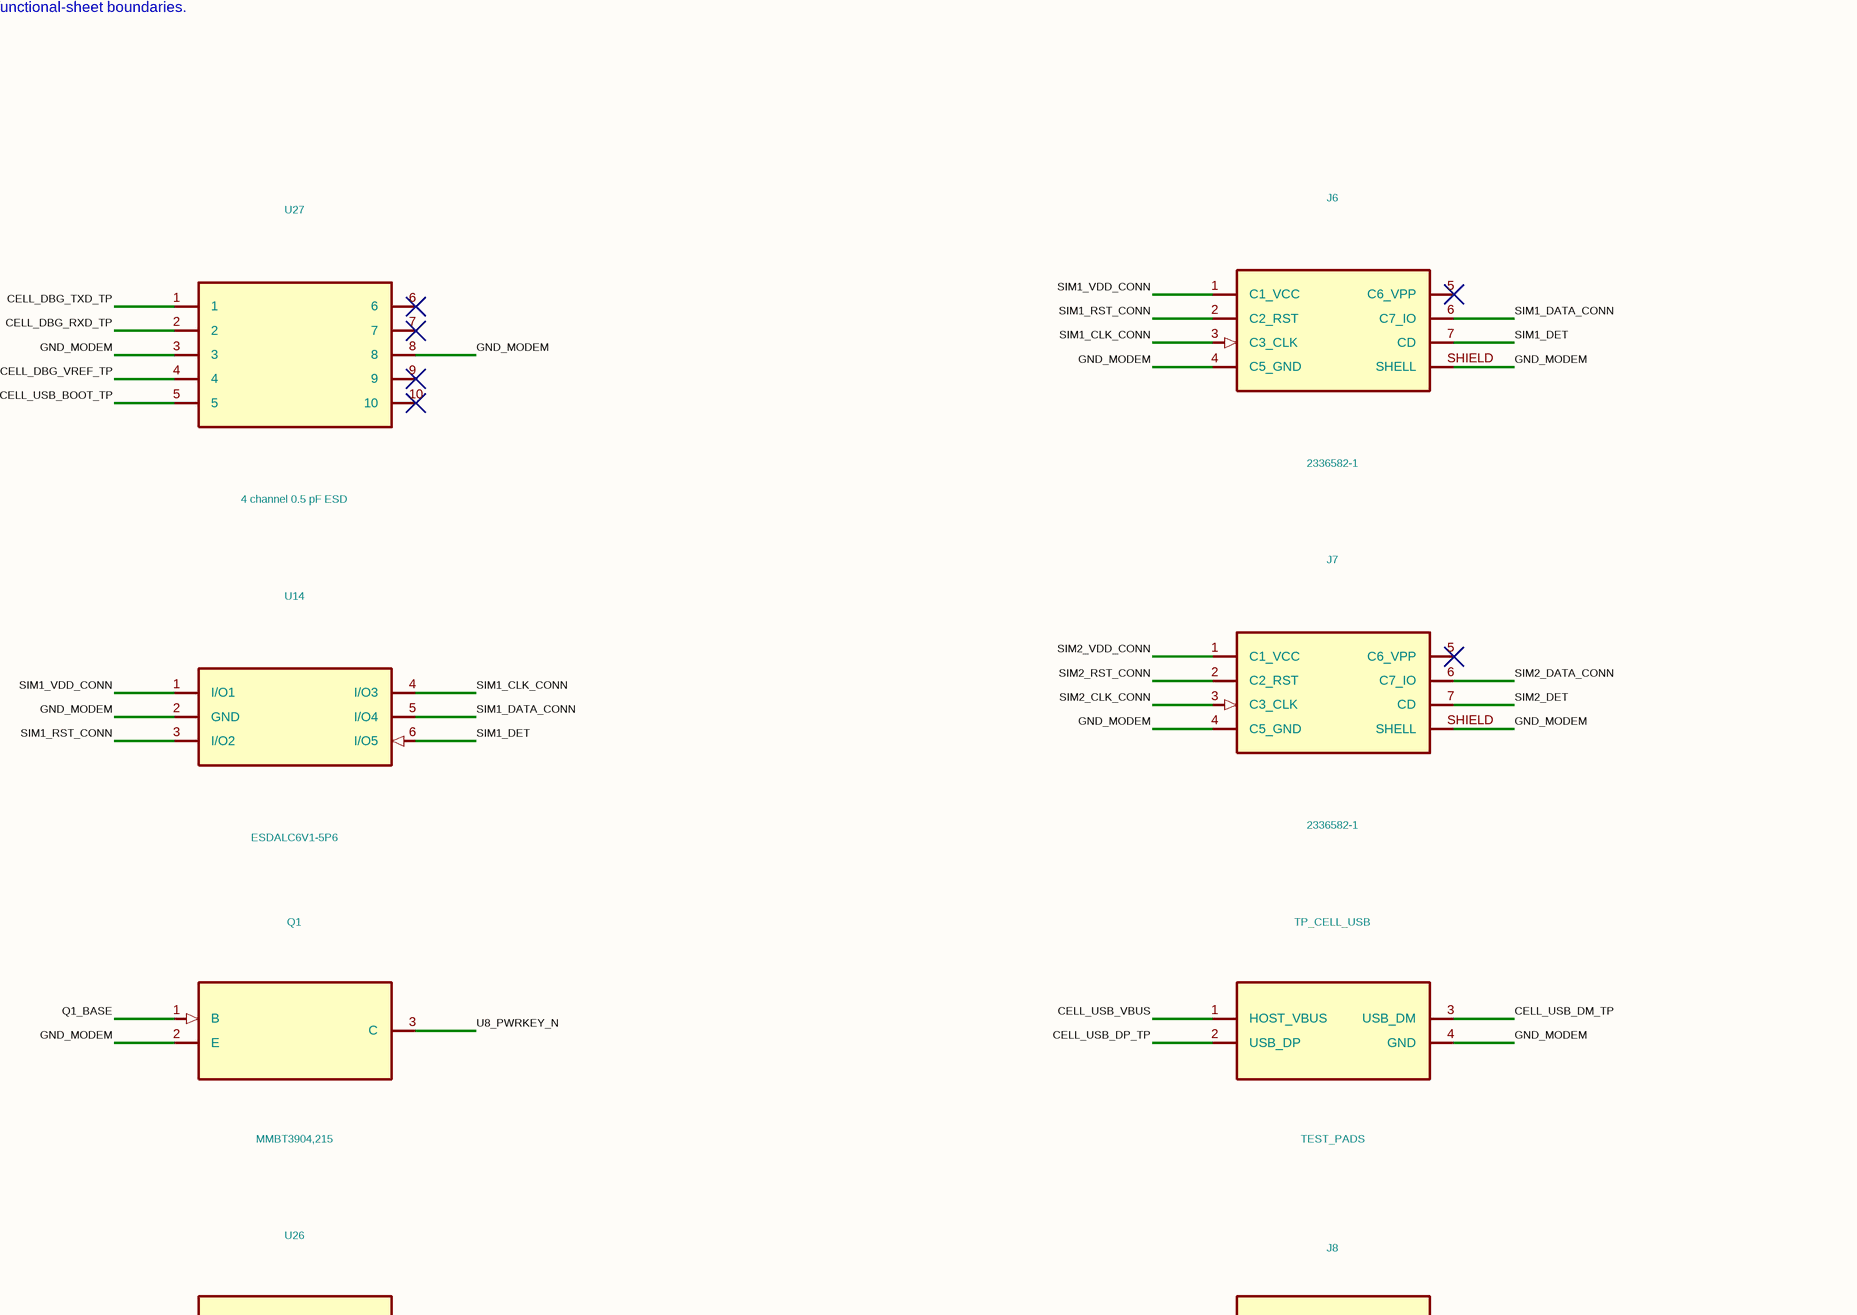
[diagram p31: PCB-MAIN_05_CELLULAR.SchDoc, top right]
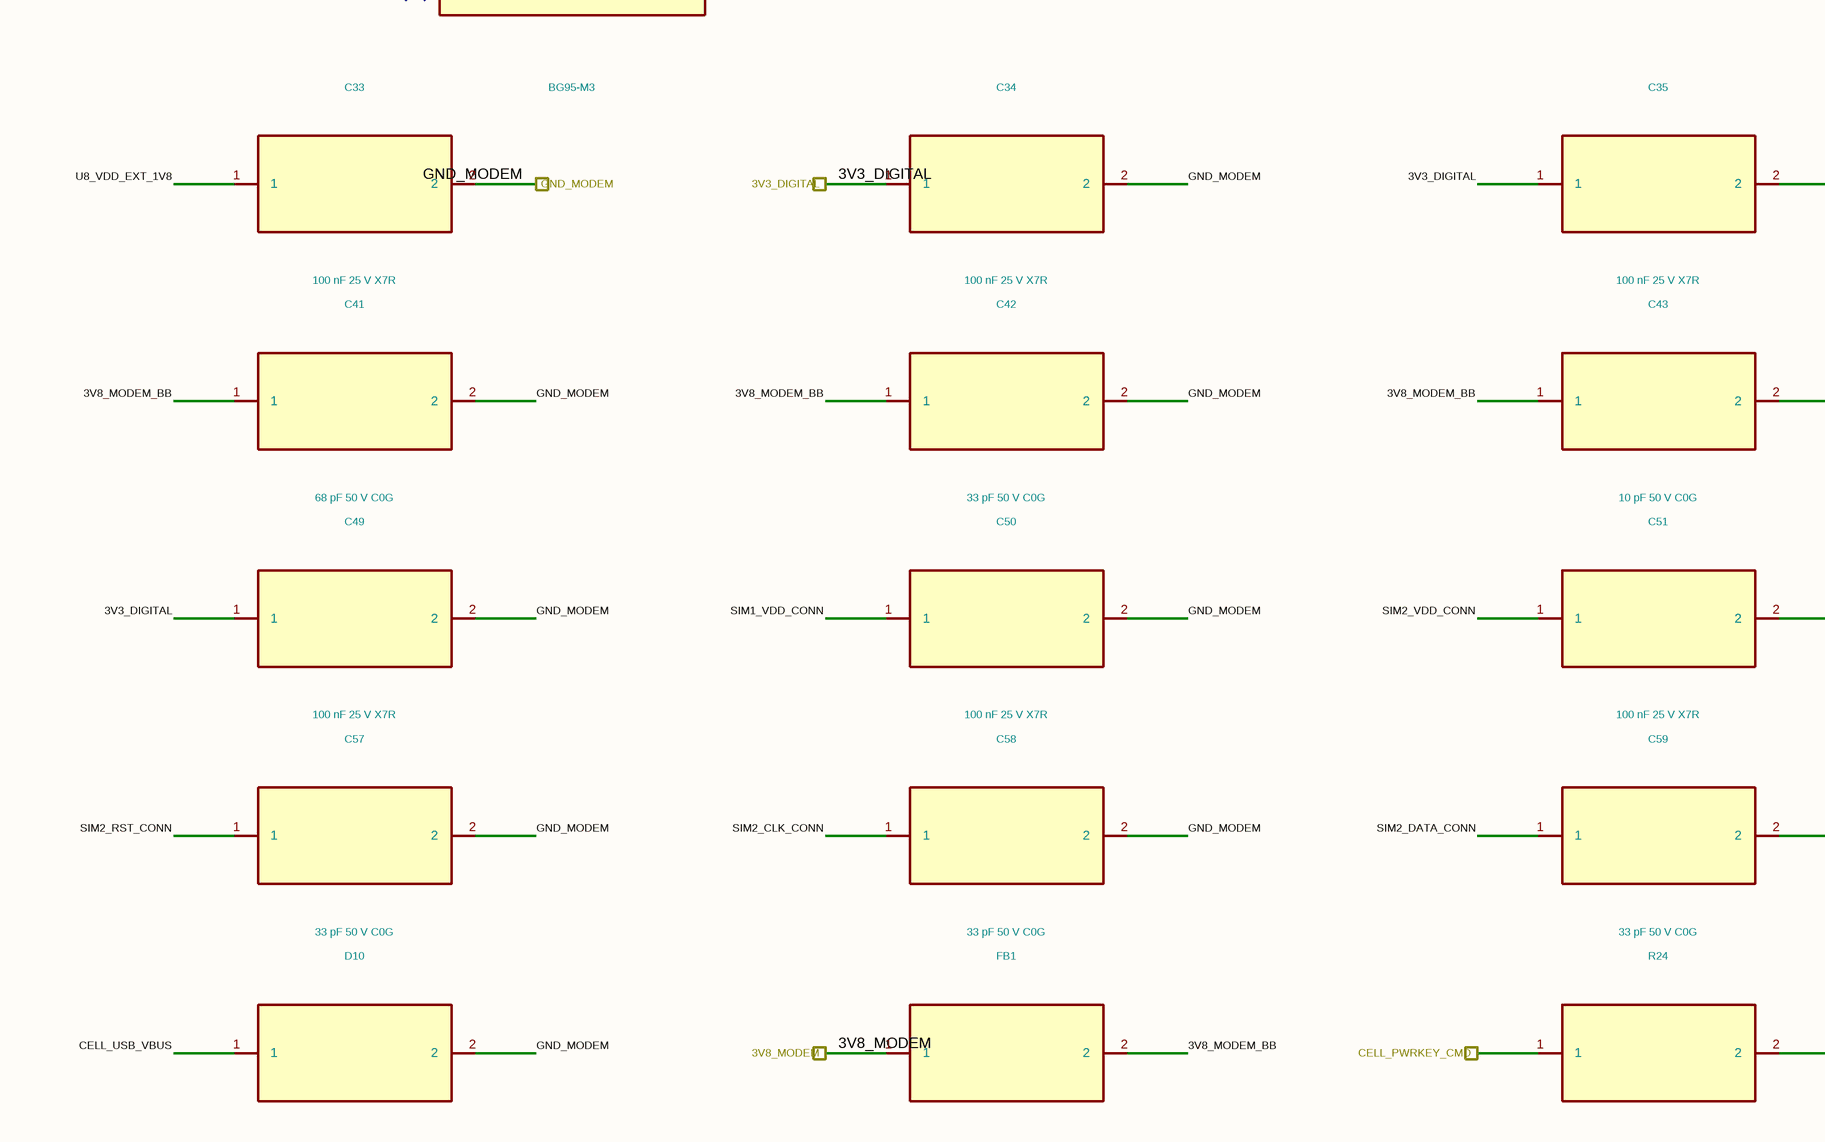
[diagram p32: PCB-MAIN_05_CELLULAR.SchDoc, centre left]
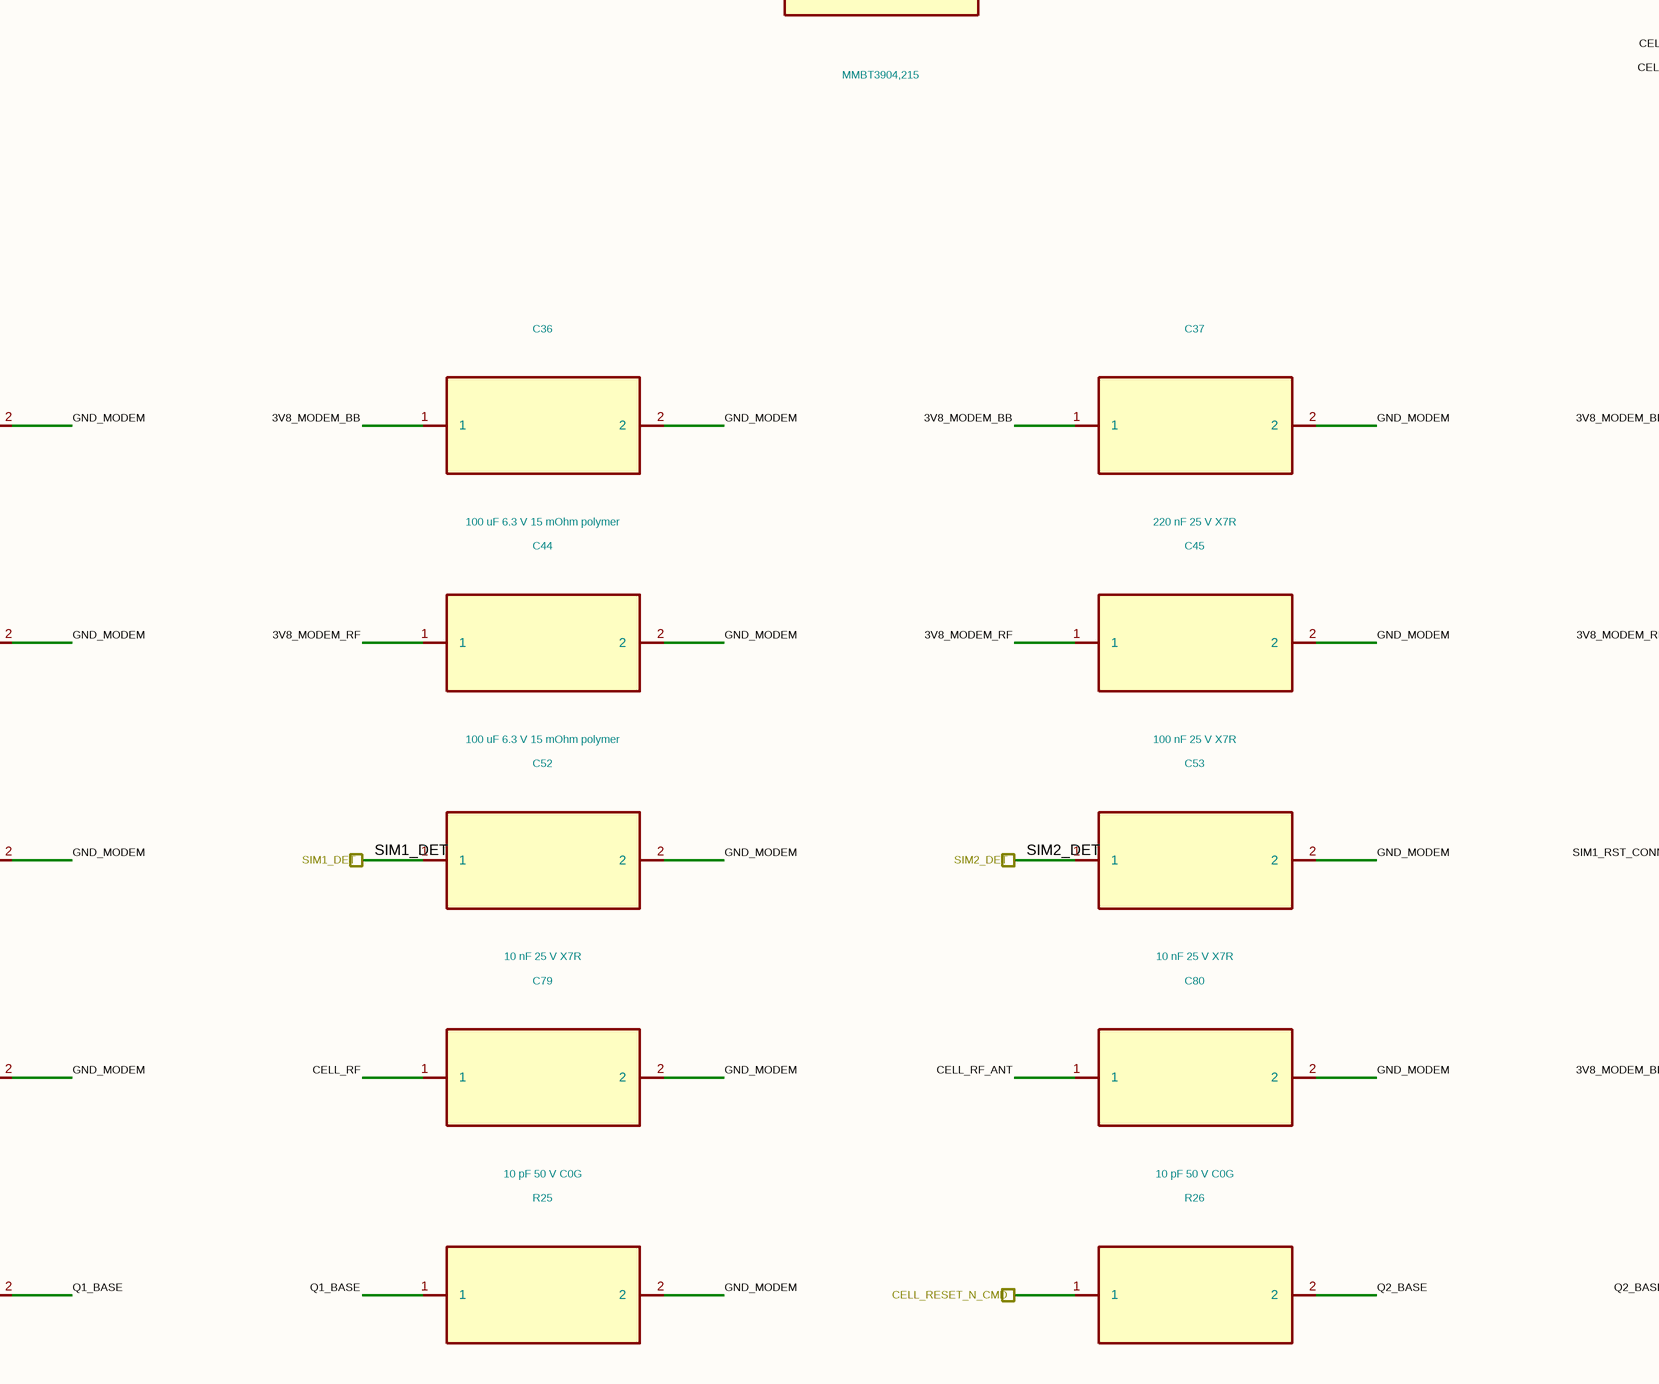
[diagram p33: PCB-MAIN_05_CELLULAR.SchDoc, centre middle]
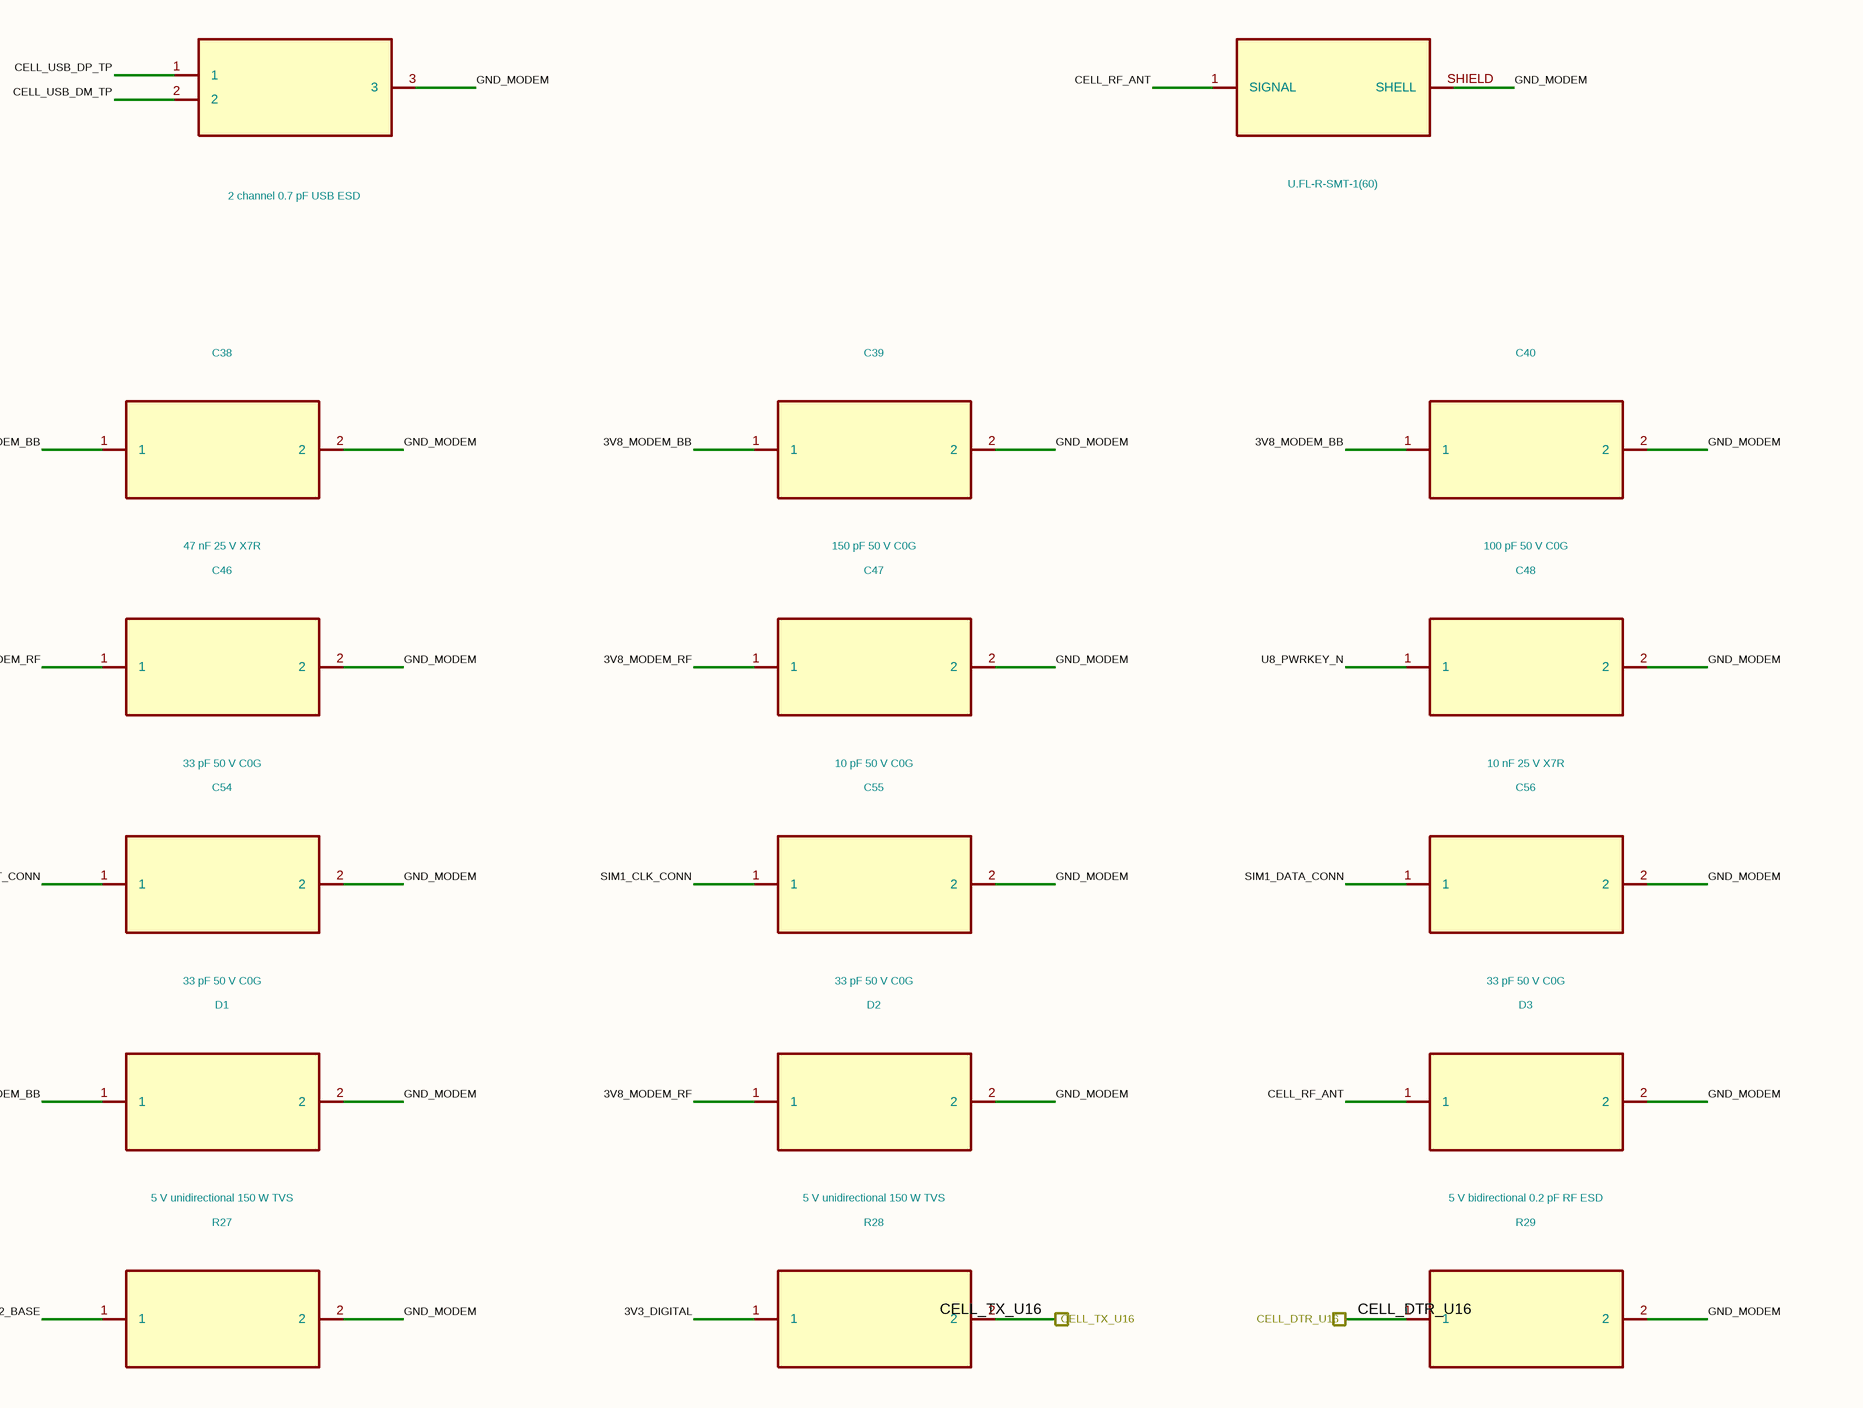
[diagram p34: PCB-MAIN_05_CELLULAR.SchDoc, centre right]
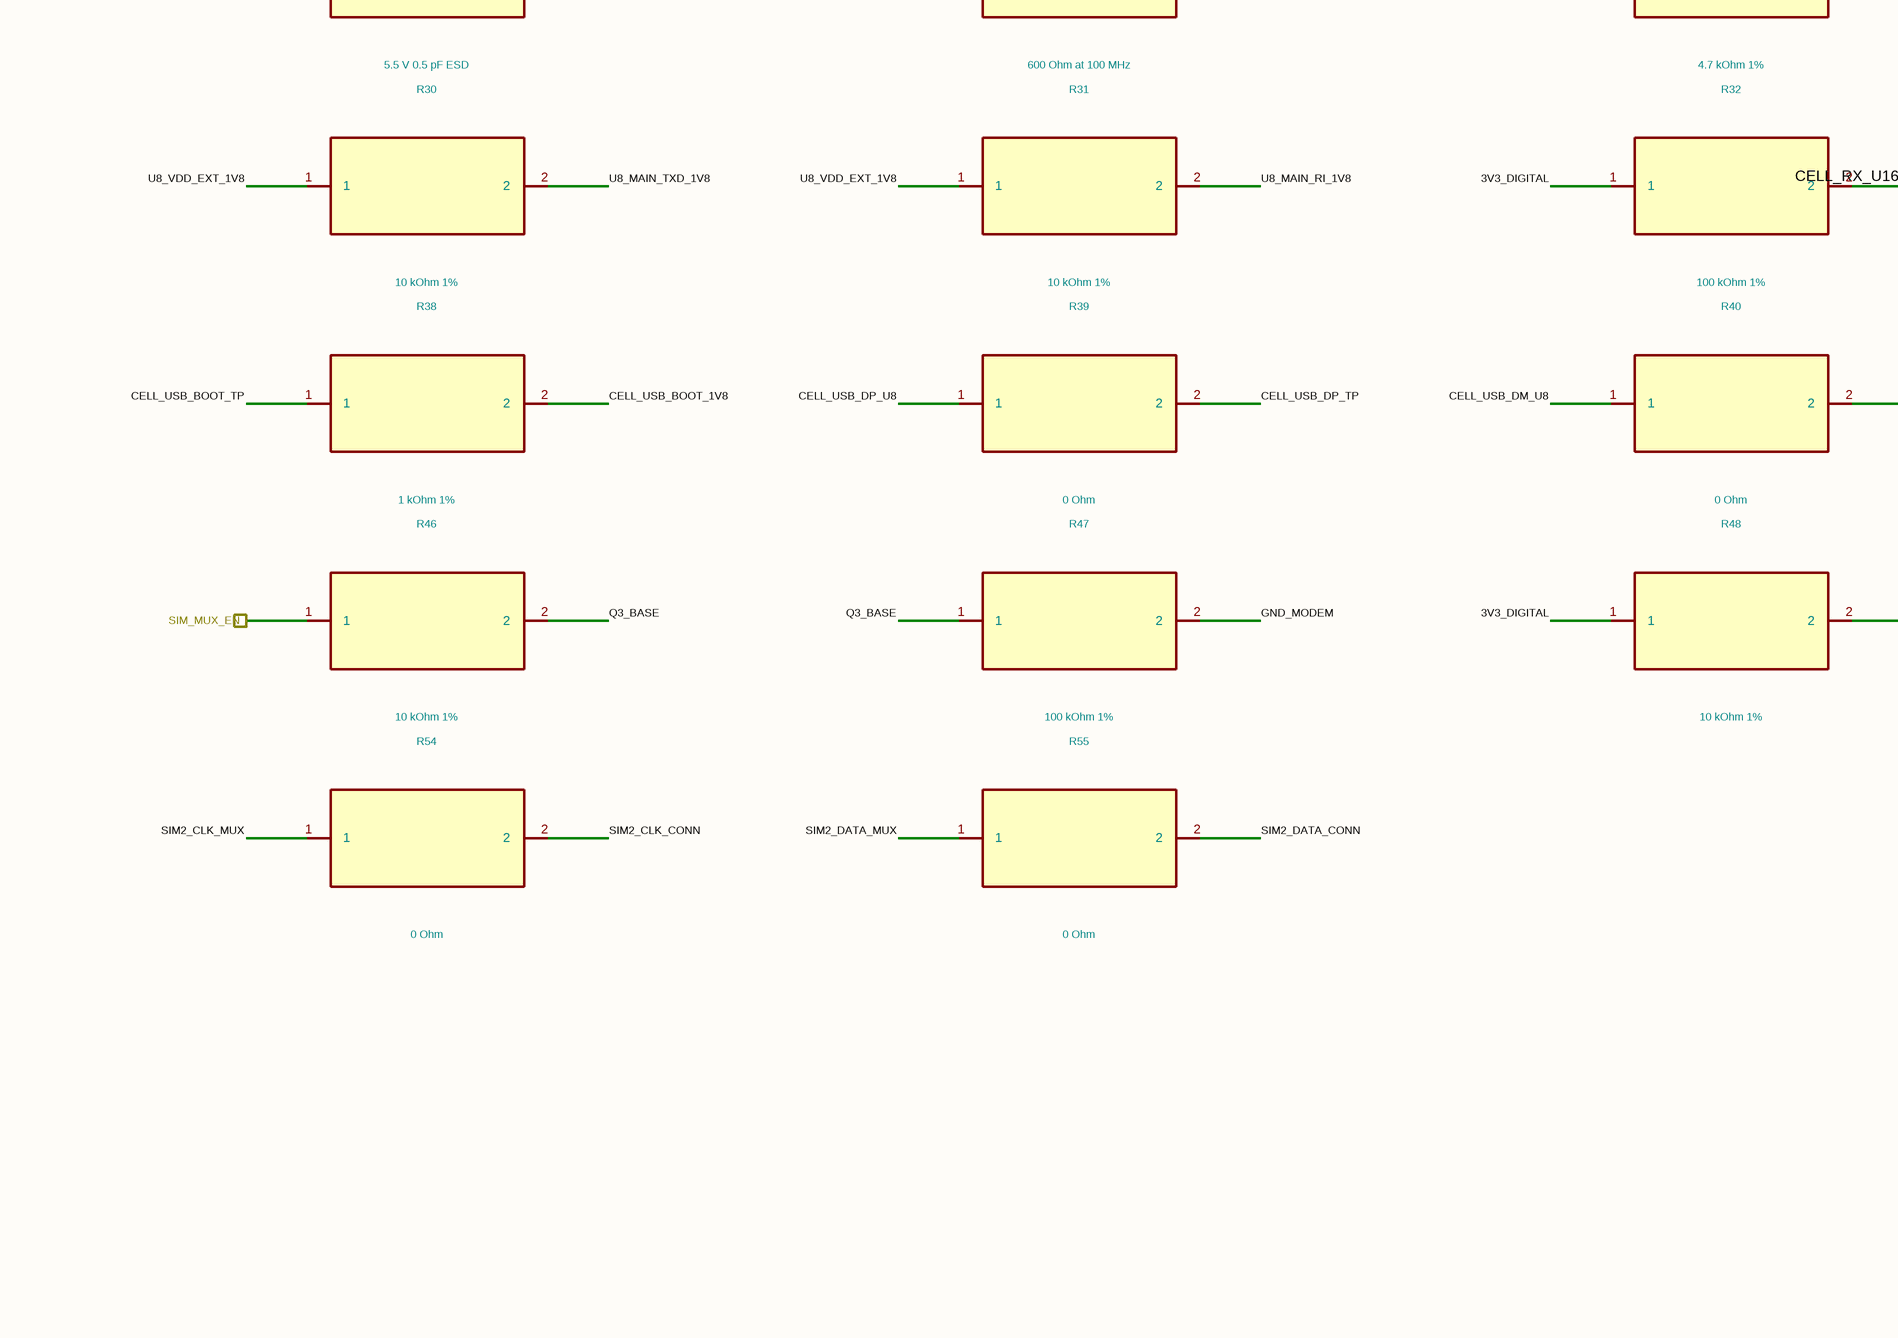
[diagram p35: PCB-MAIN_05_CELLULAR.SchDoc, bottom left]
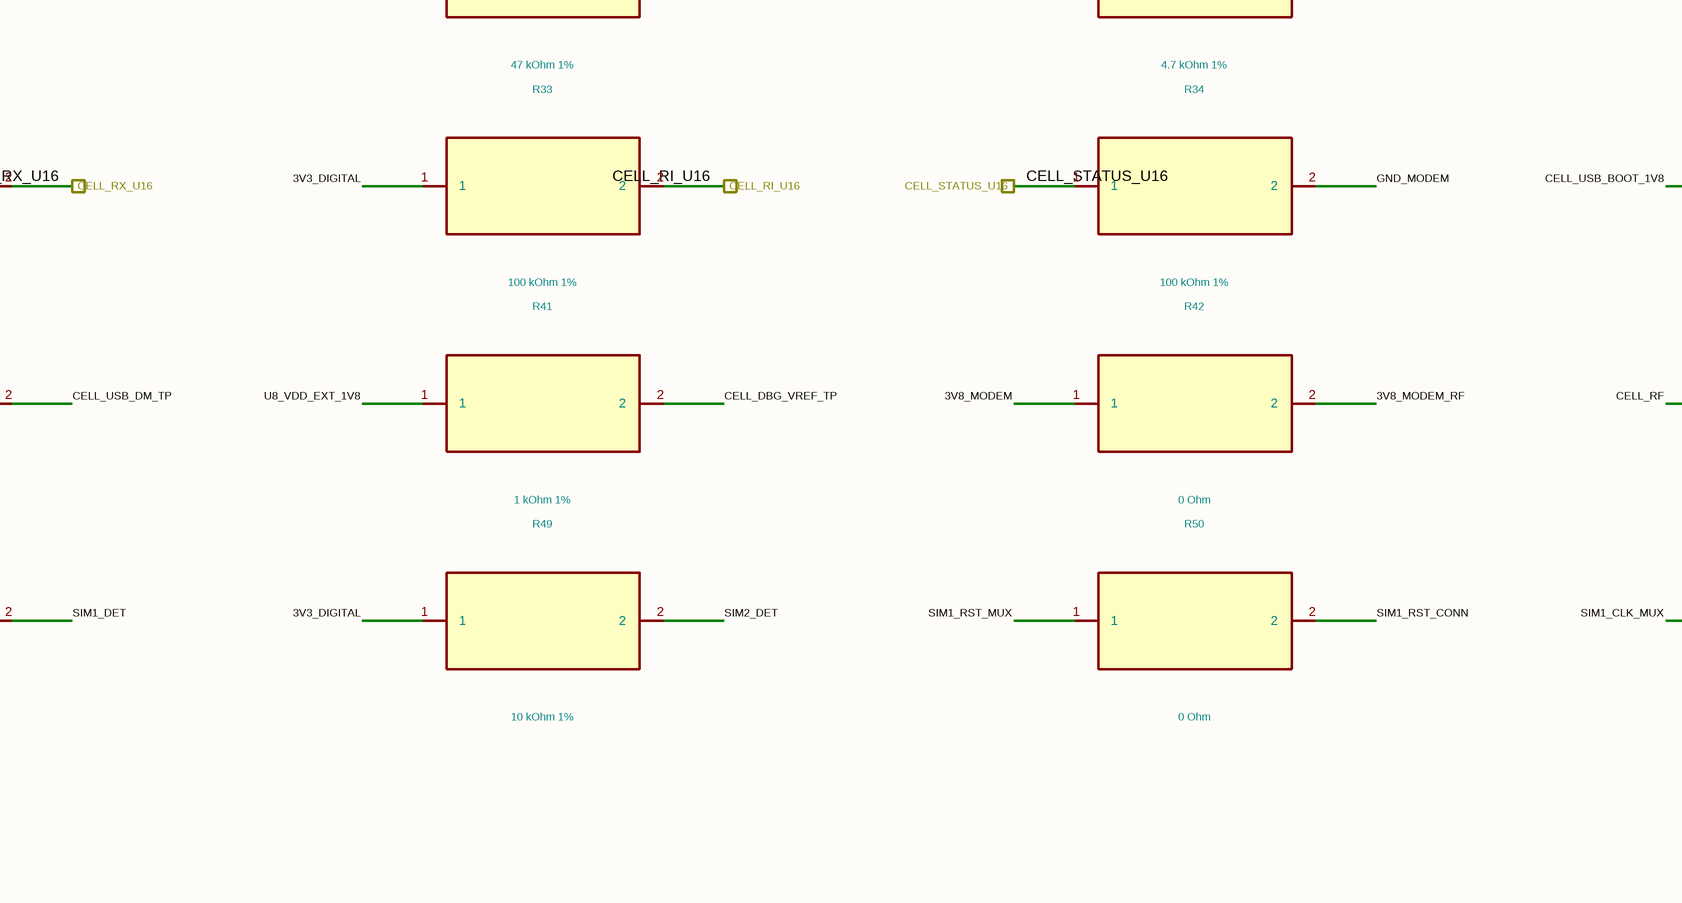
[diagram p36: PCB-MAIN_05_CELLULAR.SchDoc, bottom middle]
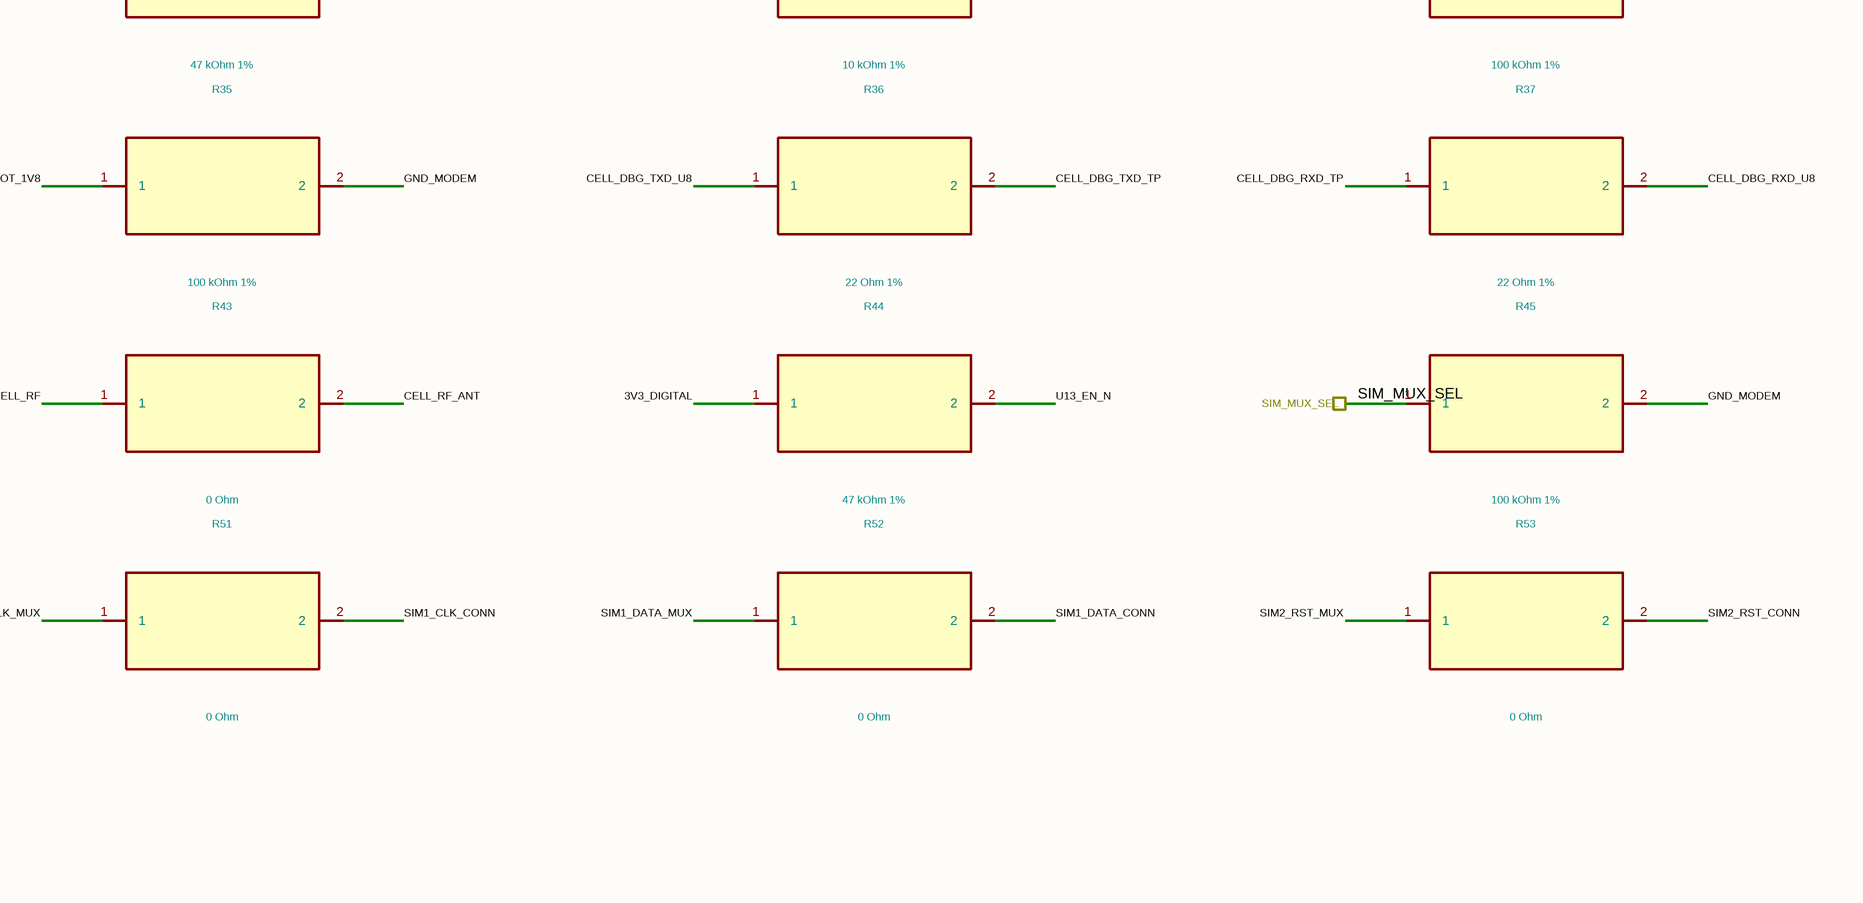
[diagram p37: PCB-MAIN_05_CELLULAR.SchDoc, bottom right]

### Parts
C33  100 nF 25 V X7R  [C_0402_1005Metric]
C34  100 nF 25 V X7R  [C_0402_1005Metric]
C35  100 nF 25 V X7R  [C_0402_1005Metric]
C36  100 uF 6.3 V 15 mOhm polymer
C37  220 nF 25 V X7R  [C_0402_1005Metric]
C38  47 nF 25 V X7R  [C_0402_1005Metric]
C39  150 pF 50 V C0G  [C_0402_1005Metric]
C40  100 pF 50 V C0G  [C_0402_1005Metric]
C41  68 pF 50 V C0G  [C_0402_1005Metric]
C42  33 pF 50 V C0G  [C_0402_1005Metric]
C43  10 pF 50 V C0G  [C_0402_1005Metric]
C44  100 uF 6.3 V 15 mOhm polymer
C45  100 nF 25 V X7R  [C_0402_1005Metric]
C46  33 pF 50 V C0G  [C_0402_1005Metric]
C47  10 pF 50 V C0G  [C_0402_1005Metric]
C48  10 nF 25 V X7R  [C_0402_1005Metric]
C49  100 nF 25 V X7R  [C_0402_1005Metric]
C50  100 nF 25 V X7R  [C_0402_1005Metric]
C51  100 nF 25 V X7R  [C_0402_1005Metric]
C52  10 nF 25 V X7R  [C_0402_1005Metric]
C53  10 nF 25 V X7R  [C_0402_1005Metric]
C54  33 pF 50 V C0G  [C_0402_1005Metric]
C55  33 pF 50 V C0G  [C_0402_1005Metric]
C56  33 pF 50 V C0G  [C_0402_1005Metric]
C57  33 pF 50 V C0G  [C_0402_1005Metric]
C58  33 pF 50 V C0G  [C_0402_1005Metric]
C59  33 pF 50 V C0G  [C_0402_1005Metric]
C79  10 pF 50 V C0G  [C_0402_1005Metric]
C80  10 pF 50 V C0G  [C_0402_1005Metric]
D1  5 V unidirectional 150 W TVS
D2  5 V unidirectional 150 W TVS
D3  5 V bidirectional 0.2 pF RF ESD
D10  5.5 V 0.5 pF ESD
FB1  600 Ohm at 100 MHz  [L_1206_3216Metric]
J6  2336582-1
J7  2336582-1
J8  U.FL-R-SMT-1(60)
Q1  MMBT3904,215
Q2  MMBT3904,215
Q3  MMBT3904,215
R24  4.7 kOhm 1%  [R_0402_1005Metric]
R25  47 kOhm 1%  [R_0402_1005Metric]
R26  4.7 kOhm 1%  [R_0402_1005Metric]
R27  47 kOhm 1%  [R_0402_1005Metric]
R28  10 kOhm 1%  [R_0402_1005Metric]
R29  100 kOhm 1%  [R_0402_1005Metric]
R30  10 kOhm 1%  [R_0402_1005Metric]
R31  10 kOhm 1%  [R_0402_1005Metric]
R32  100 kOhm 1%  [R_0402_1005Metric]
R33  100 kOhm 1%  [R_0402_1005Metric]
R34  100 kOhm 1%  [R_0402_1005Metric]
R35  100 kOhm 1%  [R_0402_1005Metric]
R36  22 Ohm 1%  [R_0402_1005Metric]
R37  22 Ohm 1%  [R_0402_1005Metric]
R38  1 kOhm 1%  [R_0402_1005Metric]
R39  0 Ohm  [R_0402_1005Metric]
R40  0 Ohm  [R_0402_1005Metric]
R41  1 kOhm 1%  [R_0402_1005Metric]
R42  0 Ohm  [R_0402_1005Metric]
R43  0 Ohm  [R_0402_1005Metric]
R44  47 kOhm 1%  [R_0402_1005Metric]
R45  100 kOhm 1%  [R_0402_1005Metric]
R46  10 kOhm 1%  [R_0402_1005Metric]
R47  100 kOhm 1%  [R_0402_1005Metric]
R48  10 kOhm 1%  [R_0402_1005Metric]
R49  10 kOhm 1%  [R_0402_1005Metric]
R50  0 Ohm  [R_0402_1005Metric]
R51  0 Ohm  [R_0402_1005Metric]
R52  0 Ohm  [R_0402_1005Metric]
R53  0 Ohm  [R_0402_1005Metric]
R54  0 Ohm  [R_0402_1005Metric]
R55  0 Ohm  [R_0402_1005Metric]
TP_CELL_DBG  TEST_PADS
TP_CELL_USB  TEST_PADS
U8  BG95-M3
U13  TS3A27518EPWR
U14  ESDALC6V1-5P6
U15  ESDALC6V1-5P6
U16  SN74AXC8T245PWR
U26  2 channel 0.7 pF USB ESD
U27  4 channel 0.5 pF ESD

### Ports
3V3_DIGITAL, 3V8_MODEM, CELL_DTR_U16, CELL_PWRKEY_CMD, CELL_RESET_N_CMD, CELL_RI_U16, CELL_RX_U16, CELL_STATUS_U16, CELL_TX_U16, GND_MODEM, SIM1_DET, SIM2_DET, SIM_MUX_EN, SIM_MUX_SEL

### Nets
3V3_DIGITAL: C34.1 C35.1 C49.1 R28.1 R32.1 R33.1 R44.1 R48.1 R49.1 U13.8(VCC) U16.23(VCCB) U16.24(VCCB) ; port 3V3_DIGITAL
3V8_MODEM: FB1.1 R42.1 ; port 3V8_MODEM
3V8_MODEM_BB: C36.1 C37.1 C38.1 C39.1 C40.1 C41.1 C42.1 C43.1 D1.1 FB1.2 U8.32(VBAT_BB) U8.33(VBAT_BB)
3V8_MODEM_RF: C44.1 C45.1 C46.1 C47.1 D2.1 R42.2 U8.52(VBAT_RF) U8.53(VBAT_RF)
CELL_DBG_RXD_TP: R37.1 TP_CELL_DBG.3(DUT_RX) U27.2
CELL_DBG_RXD_U8: R37.2 U8.22(DBG_RXD)
CELL_DBG_TXD_TP: R36.2 TP_CELL_DBG.2(DUT_TX) U27.1
CELL_DBG_TXD_U8: R36.1 U8.23(DBG_TXD)
CELL_DBG_VREF_TP: R41.2 U27.4
CELL_DTR_U16: R29.1 U16.16(B6) ; port CELL_DTR_U16
CELL_PWRKEY_CMD: R24.1 ; port CELL_PWRKEY_CMD
CELL_RESET_N_CMD: R26.1 ; port CELL_RESET_N_CMD
CELL_RF: C79.1 R43.1 U8.60(ANT_MAIN)
CELL_RF_ANT: C80.1 D3.1 J8.1(SIGNAL) R43.2
CELL_RI_U16: R33.2 U16.19(B3) ; port CELL_RI_U16
CELL_RX_U16: R32.2 U16.21(B1) ; port CELL_RX_U16
CELL_STATUS_U16: R34.1 U16.20(B2) ; port CELL_STATUS_U16
CELL_TX_U16: R28.2 U16.17(B5) ; port CELL_TX_U16
CELL_USB_BOOT_1V8: R35.1 R38.2 U8.75(USB_BOOT)
CELL_USB_BOOT_TP: R38.1 TP_CELL_DBG.4(USB_BOOT) U27.5
CELL_USB_DM_TP: R40.2 TP_CELL_USB.3(USB_DM) U26.2
CELL_USB_DM_U8: R40.1 U8.10(USB_DM)
CELL_USB_DP_TP: R39.2 TP_CELL_USB.2(USB_DP) U26.1
CELL_USB_DP_U8: R39.1 U8.9(USB_DP)
CELL_USB_VBUS: D10.1 TP_CELL_USB.1(HOST_VBUS) U8.8(USB_VBUS)
CELL_USIM_CLK_1V8: U8.46(USIM_CLK) U13.7(COM3)
CELL_USIM_DATA_1V8: U8.45(USIM_DATA) U13.10(COM5)
CELL_USIM_RST_1V8: U8.44(USIM_RST) U13.6(COM2)
CELL_USIM_VDD_1V8: U8.43(USIM_VDD) U13.4(COM1) U13.9(COM4) U13.12(COM6)
GND_MODEM: C33.2 C34.2 C35.2 C36.2 C37.2 C38.2 C39.2 C40.2 C41.2 C42.2 C43.2 C44.2 C45.2 C46.2 C47.2 C48.2 C49.2 C50.2 C51.2 C52.2 C53.2 C54.2 C55.2 C56.2 C57.2 C58.2 C59.2 C79.2 C80.2 D1.2 D2.2 D3.2 D10.2 J6.4(C5_GND) J6.SHIELD(SHELL) J7.4(C5_GND) J7.SHIELD(SHELL) J8.SHIELD(SHELL) Q1.2(E) Q2.2(E) Q3.2(E) R25.2 R27.2 R29.2 R34.2 R35.2 R45.2 R47.2 TP_CELL_DBG.5(GND) TP_CELL_USB.4(GND) U8.3(GND) U8.31(GND) U8.47(USIM_GND) U8.48(GND) U8.50(GND) U8.54(GND) U8.55(GND) U8.58(GND) U8.59(GND) U8.61(GND) U8.62(GND) U8.67(GND) U8.68(GND) U8.69(GND) U8.70(GND) U8.71(GND) U8.72(GND) U8.73(GND) U8.74(GND) U8.79(GND) U8.80(GND) U8.81(GND) U8.82(GND) U8.89(GND) U8.90(GND) U8.91(GND) U8.100(GND) U8.101(GND) U8.102(GND) U13.5(GND) U14.2(GND) U15.2(GND) U16.6(A4) U16.11(DIR2) U16.12(GND) U16.13(GND) U16.14(B8) U16.15(B7) U16.22(OE) U26.3 U27.3 U27.8 ; port GND_MODEM
Q1_BASE: Q1.1(B) R24.2 R25.1
Q2_BASE: Q2.1(B) R26.2 R27.1
Q3_BASE: Q3.1(B) R46.2 R47.1
SIM1_CLK_CONN: C55.1 J6.3(C3_CLK) R51.2 U14.4(I/O3)
SIM1_CLK_MUX: R51.1 U13.23(NC3)
SIM1_DATA_CONN: C56.1 J6.6(C7_IO) R52.2 U14.5(I/O4)
SIM1_DATA_MUX: R52.1 U13.19(NC5)
SIM1_DET: C52.1 J6.7(CD) R48.2 U14.6(I/O5) ; port SIM1_DET
SIM1_RST_CONN: C54.1 J6.2(C2_RST) R50.2 U14.3(I/O2)
SIM1_RST_MUX: R50.1 U13.1(NC2)
SIM1_VDD_CONN: C50.1 J6.1(C1_VCC) U13.2(NC1) U13.21(NC4) U13.22(NC6) U14.1(I/O1)
SIM2_CLK_CONN: C58.1 J7.3(C3_CLK) R54.2 U15.4(I/O3)
SIM2_CLK_MUX: R54.1 U13.15(NO3)
SIM2_DATA_CONN: C59.1 J7.6(C7_IO) R55.2 U15.5(I/O4)
SIM2_DATA_MUX: R55.1 U13.18(NO5)
SIM2_DET: C53.1 J7.7(CD) R49.2 U15.6(I/O5) ; port SIM2_DET
SIM2_RST_CONN: C57.1 J7.2(C2_RST) R53.2 U15.3(I/O2)
SIM2_RST_MUX: R53.1 U13.13(NO2)
SIM2_VDD_CONN: C51.1 J7.1(C1_VCC) U13.11(NO1) U13.16(NO6) U13.17(NO4) U15.1(I/O1)
SIM_MUX_EN: R46.1 ; port SIM_MUX_EN
SIM_MUX_SEL: R45.1 U13.14(IN2) U13.24(IN1) ; port SIM_MUX_SEL
U8_MAIN_DTR_1V8: U8.30(MAIN_DTR) U16.8(A6)
U8_MAIN_RI_1V8: R31.2 U8.39(MAIN_RI) U16.5(A3)
U8_MAIN_RXD_1V8: U8.34(MAIN_RXD) U16.7(A5)
U8_MAIN_TXD_1V8: R30.2 U8.35(MAIN_TXD) U16.3(A1)
U8_PWRKEY_N: C48.1 Q1.3(C) U8.15(PWRKEY)
U8_RESET_N: Q2.3(C) U8.17(RESET_N)
U8_STATUS_1V8: U8.20(STATUS) U16.4(A2)
U8_VDD_EXT_1V8: C33.1 R30.1 R31.1 R41.1 TP_CELL_DBG.1(VREF_1V8) U8.29(VDD_EXT) U16.1(VCCA) U16.2(DIR1)
U13_EN_N: Q3.3(C) R44.2 U13.20(EN)

Not connected (* = marked no-connect by the designer): J6 5(C6_VPP)*; J7 5(C6_VPP)*; U8 1(PSM_IND)* 2(ADC1)* 4(PCM_CLK)* 5(PCM_SYNC)* 6(PCM_DIN)* 7(PCM_DOUT)* 11(RESERVED)* 12(RESERVED)* 13(RESERVED)* 14(RESERVED)* 16(RESERVED)* 18(W_DISABLE#)* 19(AP_READY)* 21(NET_STATUS)* 24(ADC0)* 25(GPIO1)* 26(GPIO2)* 27(GNSS_TXD)* 28(GNSS_RXD)* 36(MAIN_CTS)* 37(MAIN_RTS)* 38(MAIN_DCD)* 40(I2C_SCL)* 41(I2C_SDA)* 42(USIM_DET)* 49(ANT_GNSS)* 51(GNSS_LNA_EN)* 56(ANT_WIFI)* 57(RESERVED)* 63(RESERVED)* 64(GPIO3)* 65(GPIO4)* 66(GPIO5)* 76(RESERVED)* 77(RESERVED)* 78(RESERVED)* 83(GRFC1)* 84(GRFC2)* 85(GPIO6)* 86(GPIO7)* 87(GPIO8)* 88(GPIO9)* 92(RESERVED)* 93(RESERVED)* 94(RESERVED)* 95(RESERVED)* 96(PON_TRIG)* 97(RESERVED)* 98(RESERVED)* 99(RESERVED)*; U13 3(N.C.)*; U16 9(A7)* 10(A8)* 18(B4)*; U27 6* 7* 9* 10*

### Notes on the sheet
- Every connected symbol pin has one explicit wire stub. Only hierarchical labels cross functional-sheet boundaries.

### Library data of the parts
C33 = C33_GRM155R71E104KE14D: Manufacturer: Murata; Population: FITTED; Authority: TI_SCES875C_RevC
C34 = C34_GRM155R71E104KE14D: Manufacturer: Murata; Population: FITTED; Authority: TI_SCES875C_RevC
C35 = C35_GRM155R71E104KE14D: Manufacturer: Murata; Population: FITTED; Authority: TI_SCES875C_RevC
C36 = C36_T520D107M006ATE015: Manufacturer: KEMET; Population: FITTED; Authority: Quectel_BG95_HW_Design_v1.6
C37 = C37_GRM155R71E224KE14D: Manufacturer: Murata; Population: FITTED; Authority: Quectel_BG95_HW_Design_v1.6
C38 = C38_GRM155R71E473KA01D: Manufacturer: Murata; Population: FITTED; Authority: Quectel_BG95_HW_Design_v1.6
C39 = C39_GRM1555C1H151JA01D: Manufacturer: Murata; Population: FITTED; Authority: Quectel_BG95_HW_Design_v1.6
C40 = C40_GRM1555C1H101JA01D: Manufacturer: Murata; Population: FITTED; Authority: Quectel_BG95_HW_Design_v1.6
C41 = C41_GRM1555C1H680JA01D: Manufacturer: Murata; Population: FITTED; Authority: Quectel_BG95_HW_Design_v1.6
C42 = C42_GRM1555C1H330JA01D: Manufacturer: Murata; Population: FITTED; Authority: Quectel_BG95_HW_Design_v1.6
C43 = C43_GRM1555C1H100JA01D: Manufacturer: Murata; Population: FITTED; Authority: Quectel_BG95_HW_Design_v1.6
C44 = C44_T520D107M006ATE015: Manufacturer: KEMET; Population: FITTED; Authority: Quectel_BG95_HW_Design_v1.6
C45 = C45_GRM155R71E104KE14D: Manufacturer: Murata; Population: FITTED; Authority: Quectel_BG95_HW_Design_v1.6
C46 = C46_GRM1555C1H330JA01D: Manufacturer: Murata; Population: FITTED; Authority: Quectel_BG95_HW_Design_v1.6
C47 = C47_GRM1555C1H100JA01D: Manufacturer: Murata; Population: FITTED; Authority: Quectel_BG95_HW_Design_v1.6
C48 = C48_GRM155R71E103KA01D: Manufacturer: Murata; Population: FITTED; Authority: Quectel_BG95_HW_Design_v1.6
C49 = C49_GRM155R71E104KE14D: Manufacturer: Murata; Population: FITTED; Authority: TI_TS3A27518E_SCDS260F
C50 = C50_GRM155R71E104KE14D: Manufacturer: Murata; Population: FITTED; Authority: Quectel_BG95_HW_Design_v1.6
C51 = C51_GRM155R71E104KE14D: Manufacturer: Murata; Population: FITTED; Authority: Quectel_BG95_HW_Design_v1.6
C52 = C52_GRM155R71E103KA01D: Manufacturer: Murata; Population: FITTED; Authority: TE_C-2336582_A2
C53 = C53_GRM155R71E103KA01D: Manufacturer: Murata; Population: FITTED; Authority: TE_C-2336582_A2
C54 = C54_GRM1555C1H330JA01D: Manufacturer: Murata; Population: DNP; Authority: Quectel_BG95_HW_Design_v1.6
C55 = C55_GRM1555C1H330JA01D: Manufacturer: Murata; Population: DNP; Authority: Quectel_BG95_HW_Design_v1.6
C56 = C56_GRM1555C1H330JA01D: Manufacturer: Murata; Population: DNP; Authority: Quectel_BG95_HW_Design_v1.6
C57 = C57_GRM1555C1H330JA01D: Manufacturer: Murata; Population: DNP; Authority: Quectel_BG95_HW_Design_v1.6
C58 = C58_GRM1555C1H330JA01D: Manufacturer: Murata; Population: DNP; Authority: Quectel_BG95_HW_Design_v1.6
C59 = C59_GRM1555C1H330JA01D: Manufacturer: Murata; Population: DNP; Authority: Quectel_BG95_HW_Design_v1.6
C79 = C79_GRM1555C1H100JA01D: Manufacturer: Murata; Population: DNP; Authority: Quectel_BG95_HW_Design_v1.6
C80 = C80_GRM1555C1H100JA01D: Manufacturer: Murata; Population: DNP; Authority: Quectel_BG95_HW_Design_v1.6
D1 = D1_PESD5V0S1UL: Manufacturer: Nexperia; Population: FITTED; Authority: Nexperia_PESD5V0S1UL_v5
D2 = D2_PESD5V0S1UL: Manufacturer: Nexperia; Population: FITTED; Authority: Nexperia_PESD5V0S1UL_v5
D3 = D3_PESD5V0C1BSF: Manufacturer: Nexperia; Population: FITTED; Authority: Nexperia_PESD5V0C1BSF_v3
D10 = D10_TPD1E05U06DYAR: Manufacturer: Texas Instruments; Population: FITTED; Authority: TI_TPDxE05U06_RevO
FB1 = FB1_BLM31KN601SN1L: Manufacturer: Murata; Population: FITTED; Authority: Quectel_BG95_HW_Design_v1.6
J6 = J6_2336582-1: Manufacturer: CONTROLLED_AUTHORITY; Population: FITTED; Authority: PCB_MAIN_DUAL_SIM_PIN_AUTHORITY_REV_A.csv
J7 = J7_2336582-1: Manufacturer: CONTROLLED_AUTHORITY; Population: FITTED; Authority: PCB_MAIN_DUAL_SIM_PIN_AUTHORITY_REV_A.csv
J8 = J8_U.FL-R-SMT-1_60: Manufacturer: CONTROLLED_AUTHORITY; Population: FITTED; Authority: PCB_MAIN_CONNECTOR_FIXTURE_PIN_AUTHORITY_REV_A.csv
Q1 = Q1_MMBT3904_215: Manufacturer: Nexperia; Population: FITTED; Authority: PCB_MAIN_CELLULAR_PIN_AUTHORITY_REV_A.csv
Q2 = Q2_MMBT3904_215: Manufacturer: Nexperia; Population: FITTED; Authority: PCB_MAIN_CELLULAR_PIN_AUTHORITY_REV_A.csv
Q3 = Q3_MMBT3904_215: Manufacturer: Nexperia; Population: FITTED; Authority: PCB_MAIN_DUAL_SIM_PIN_AUTHORITY_REV_A.csv
R24 = R24_ERJ-2RKF4701X: Manufacturer: Panasonic; Population: FITTED; Authority: Quectel_BG95_HW_Design_v1.6
R25 = R25_ERJ-2RKF4702X: Manufacturer: Panasonic; Population: FITTED; Authority: Quectel_BG95_HW_Design_v1.6
R26 = R26_ERJ-2RKF4701X: Manufacturer: Panasonic; Population: FITTED; Authority: Quectel_BG95_HW_Design_v1.6
R27 = R27_ERJ-2RKF4702X: Manufacturer: Panasonic; Population: FITTED; Authority: Quectel_BG95_HW_Design_v1.6
R28 = R28_ERJ-2RKF1002X: Manufacturer: Panasonic; Population: FITTED; Authority: Quectel_BG95_HW_Design_v1.6
R29 = R29_ERJ-2RKF1003X: Manufacturer: Panasonic; Population: FITTED; Authority: Quectel_BG95_HW_Design_v1.6
R30 = R30_ERJ-2RKF1002X: Manufacturer: Panasonic; Population: FITTED; Authority: Quectel_BG95_HW_Design_v1.6
R31 = R31_ERJ-2RKF1002X: Manufacturer: Panasonic; Population: FITTED; Authority: Quectel_BG95_HW_Design_v1.6
R32 = R32_ERJ-2RKF1003X: Manufacturer: Panasonic; Population: FITTED; Authority: Quectel_BG95_HW_Design_v1.6
R33 = R33_ERJ-2RKF1003X: Manufacturer: Panasonic; Population: FITTED; Authority: Quectel_BG95_HW_Design_v1.6
R34 = R34_ERJ-2RKF1003X: Manufacturer: Panasonic; Population: FITTED; Authority: Quectel_BG95_HW_Design_v1.6
R35 = R35_ERJ-2RKF1003X: Manufacturer: Panasonic; Population: FITTED; Authority: Quectel_BG95_HW_Design_v1.6
R36 = R36_ERJ-2RKF22R0X: Manufacturer: Panasonic; Population: FITTED; Authority: PROJECT_MAIN_AUTH_010
R37 = R37_ERJ-2RKF22R0X: Manufacturer: Panasonic; Population: FITTED; Authority: PROJECT_MAIN_AUTH_010
R38 = R38_ERJ-2RKF1001X: Manufacturer: Panasonic; Population: FITTED; Authority: Quectel_BG95_HW_Design_v1.6
R39 = R39_ERJ-2GE0R00X: Manufacturer: Panasonic; Population: FITTED; Authority: Quectel_BG95_HW_Design_v1.6
R40 = R40_ERJ-2GE0R00X: Manufacturer: Panasonic; Population: FITTED; Authority: Quectel_BG95_HW_Design_v1.6
R41 = R41_ERJ-2RKF1001X: Manufacturer: Panasonic; Population: FITTED; Authority: PROJECT_MAIN_AUTH_010
R42 = R42_ERJ-2GE0R00X: Manufacturer: Panasonic; Population: FITTED; Authority: Quectel_BG95_HW_Design_v1.6
R43 = R43_ERJ-2GE0R00X: Manufacturer: Panasonic; Population: FITTED; Authority: Quectel_BG95_HW_Design_v1.6
R44 = R44_ERJ-2RKF4702X: Manufacturer: Panasonic; Population: FITTED; Authority: TI_TS3A27518E_SCDS260F
R45 = R45_ERJ-2RKF1003X: Manufacturer: Panasonic; Population: FITTED; Authority: TI_TS3A27518E_SCDS260F
R46 = R46_ERJ-2RKF1002X: Manufacturer: Panasonic; Population: FITTED; Authority: TI_TS3A27518E_SCDS260F
R47 = R47_ERJ-2RKF1003X: Manufacturer: Panasonic; Population: FITTED; Authority: TI_TS3A27518E_SCDS260F
R48 = R48_ERJ-2RKF1002X: Manufacturer: Panasonic; Population: FITTED; Authority: TE_C-2336582_A2
R49 = R49_ERJ-2RKF1002X: Manufacturer: Panasonic; Population: FITTED; Authority: TE_C-2336582_A2
R50 = R50_ERJ-2GE0R00X: Manufacturer: Panasonic; Population: FITTED; Authority: Quectel_BG95_HW_Design_v1.6
R51 = R51_ERJ-2GE0R00X: Manufacturer: Panasonic; Population: FITTED; Authority: Quectel_BG95_HW_Design_v1.6
R52 = R52_ERJ-2GE0R00X: Manufacturer: Panasonic; Population: FITTED; Authority: Quectel_BG95_HW_Design_v1.6
R53 = R53_ERJ-2GE0R00X: Manufacturer: Panasonic; Population: FITTED; Authority: Quectel_BG95_HW_Design_v1.6
R54 = R54_ERJ-2GE0R00X: Manufacturer: Panasonic; Population: FITTED; Authority: Quectel_BG95_HW_Design_v1.6
R55 = R55_ERJ-2GE0R00X: Manufacturer: Panasonic; Population: FITTED; Authority: Quectel_BG95_HW_Design_v1.6
TP_CELL_DBG = TP_CELL_DBG_TEST_PADS: Manufacturer: CONTROLLED_AUTHORITY; Population: FITTED; Authority: PCB_MAIN_CONNECTOR_FIXTURE_PIN_AUTHORITY_REV_A.csv
TP_CELL_USB = TP_CELL_USB_TEST_PADS: Manufacturer: CONTROLLED_AUTHORITY; Population: FITTED; Authority: PCB_MAIN_CONNECTOR_FIXTURE_PIN_AUTHORITY_REV_A.csv
U8 = U8_BG95-M3: Manufacturer: Quectel; Population: FITTED; Authority: PCB_MAIN_CELLULAR_PIN_AUTHORITY_REV_A.csv
U13 = U13_TS3A27518EPWR: Manufacturer: Texas Instruments; Population: FITTED; Authority: PCB_MAIN_DUAL_SIM_PIN_AUTHORITY_REV_A.csv
U14 = U14_ESDALC6V1-5P6: Manufacturer: STMicroelectronics; Population: FITTED; Authority: PCB_MAIN_DUAL_SIM_PIN_AUTHORITY_REV_A.csv
U15 = U15_ESDALC6V1-5P6: Manufacturer: STMicroelectronics; Population: FITTED; Authority: PCB_MAIN_DUAL_SIM_PIN_AUTHORITY_REV_A.csv
U16 = U16_SN74AXC8T245PWR: Manufacturer: Texas Instruments; Population: FITTED; Authority: PCB_MAIN_CELLULAR_PIN_AUTHORITY_REV_A.csv
U26 = U26_TPD2EUSB30DRTR: Manufacturer: Texas Instruments; Population: FITTED; Authority: TI_TPD2EUSB30_datasheet
U27 = U27_TPD4E05U06DQAR: Manufacturer: Texas Instruments; Population: FITTED; Authority: TI_TPDxE05U06_RevO

## Sheet PCB-MAIN_06_LORA.SchDoc
size 594 x 420 mm
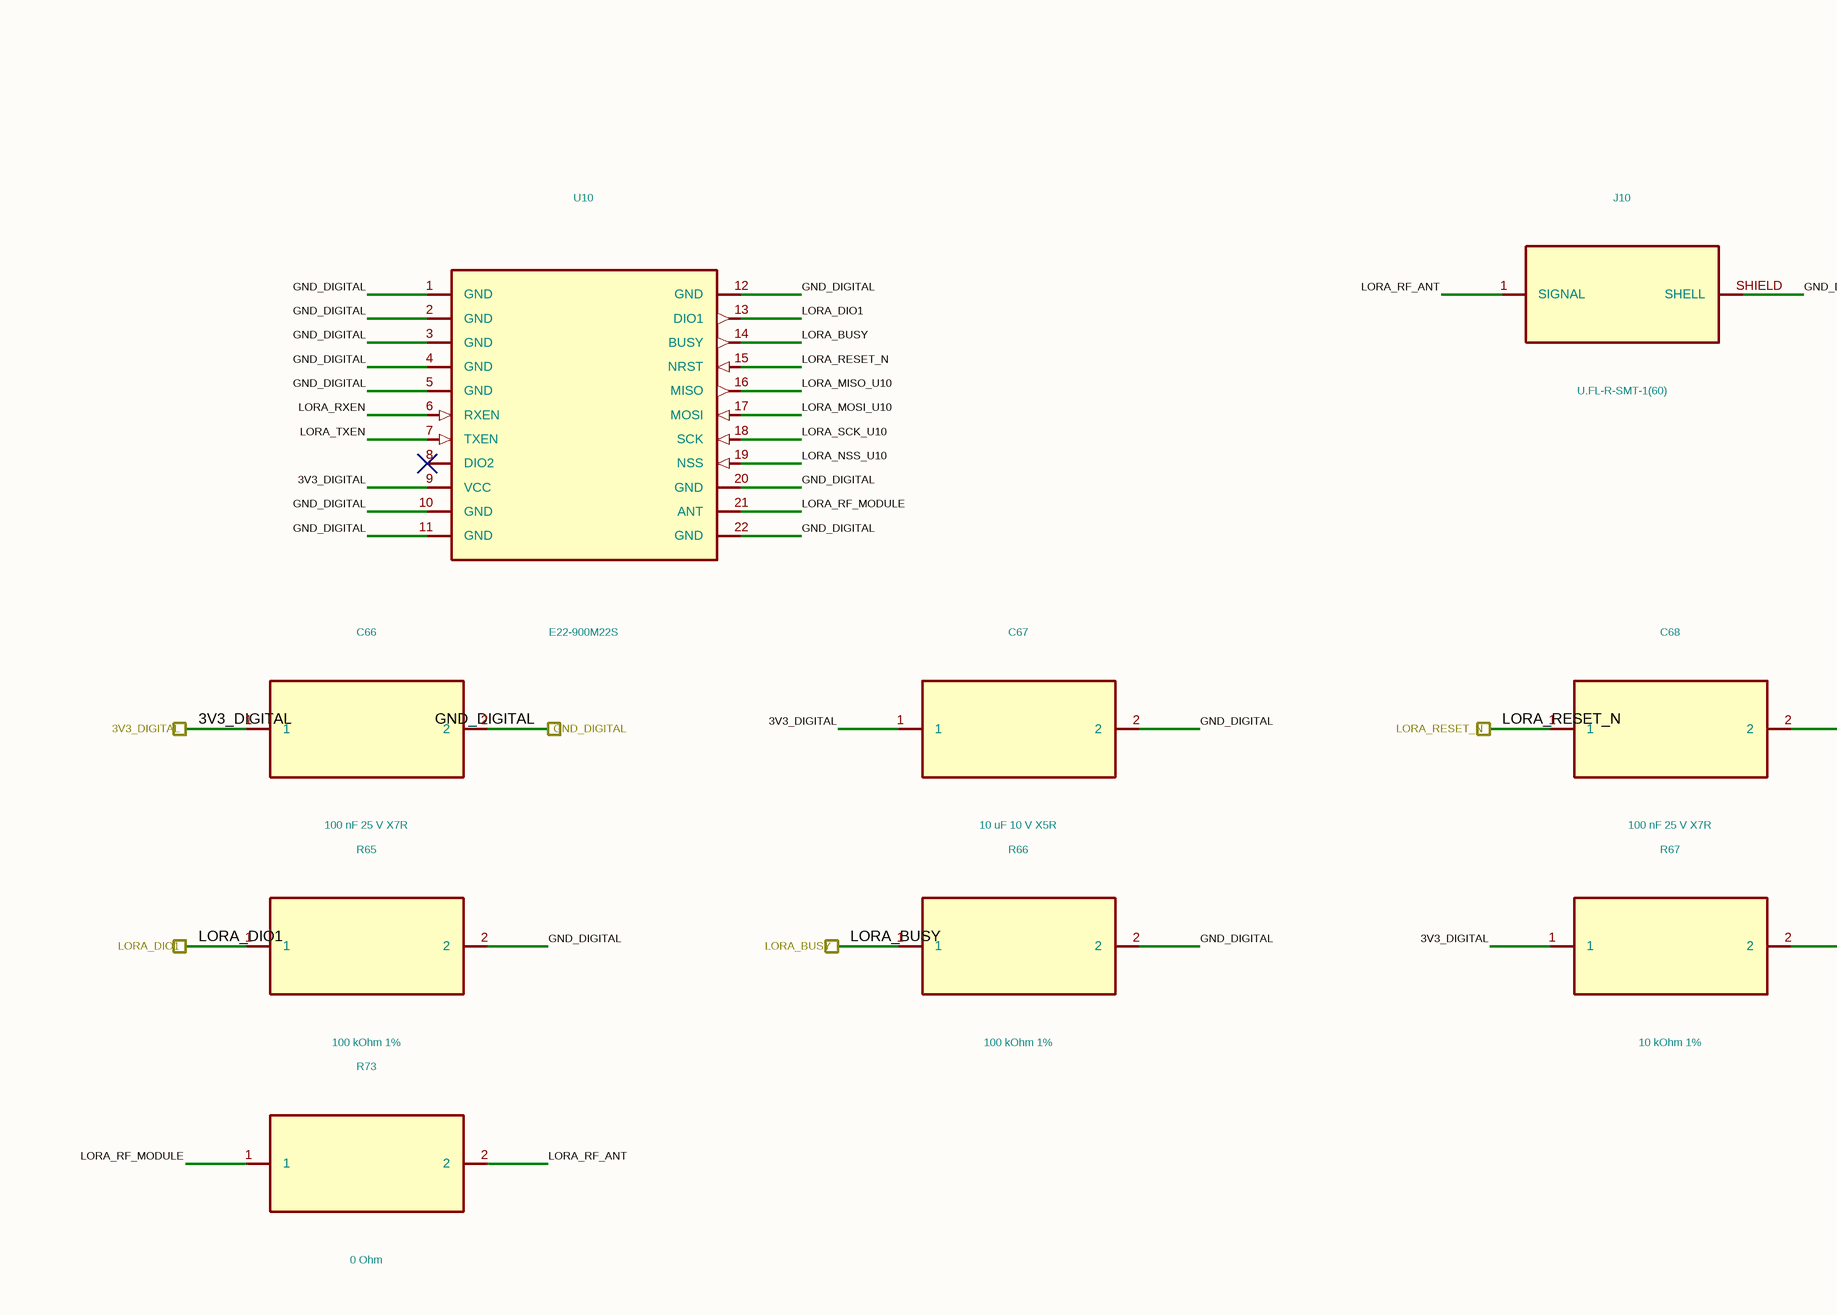
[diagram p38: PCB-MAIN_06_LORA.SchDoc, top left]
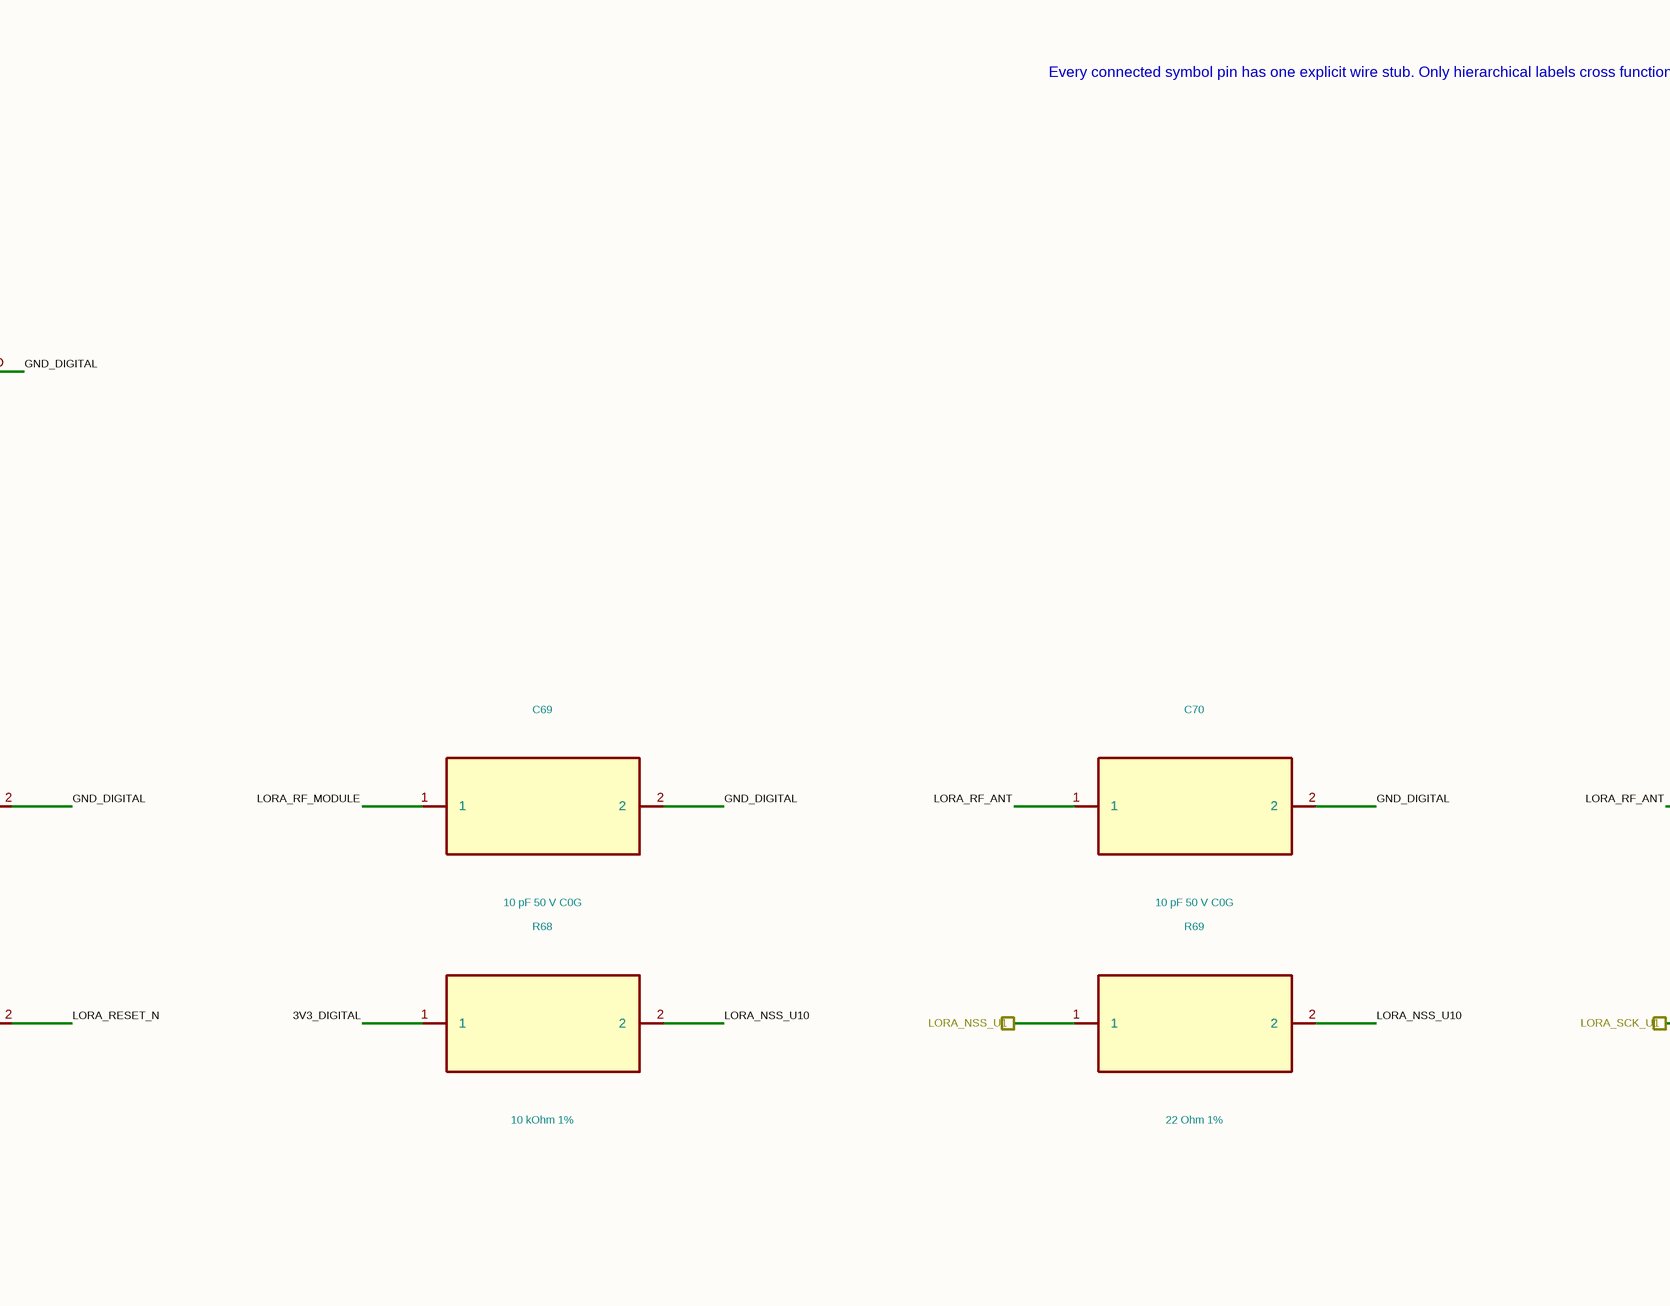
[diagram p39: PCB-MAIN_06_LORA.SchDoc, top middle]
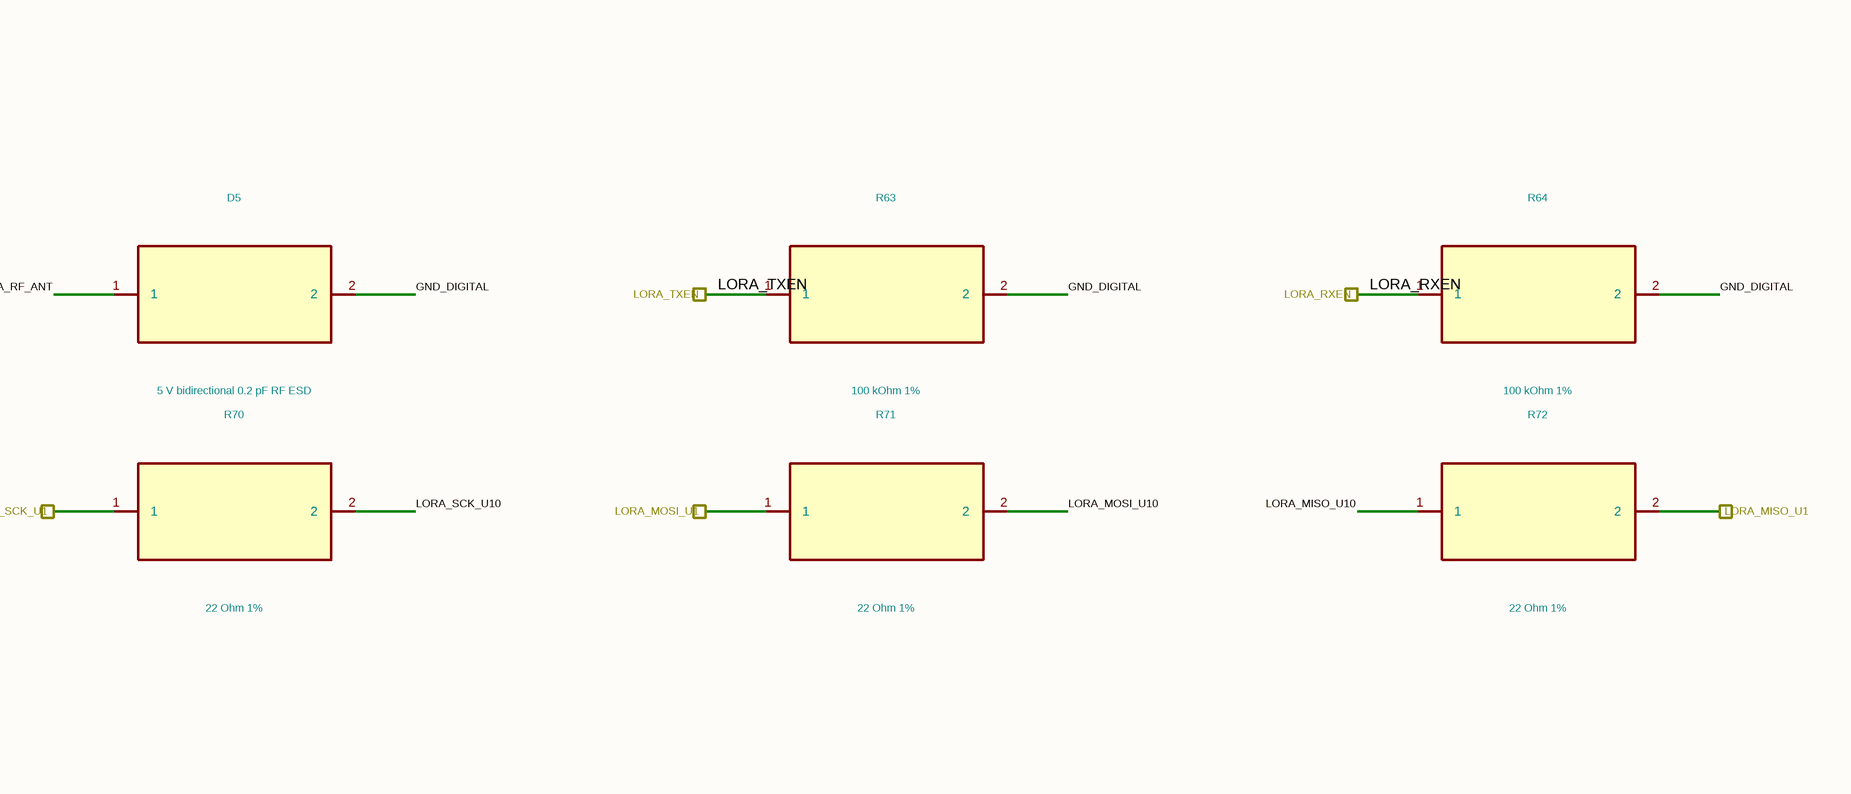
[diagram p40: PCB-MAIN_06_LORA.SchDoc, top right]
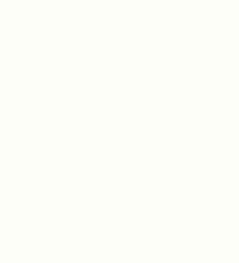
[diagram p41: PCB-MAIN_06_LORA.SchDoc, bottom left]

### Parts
C66  100 nF 25 V X7R  [C_0402_1005Metric]
C67  10 uF 10 V X5R  [C_0603_1608Metric]
C68  100 nF 25 V X7R  [C_0402_1005Metric]
C69  10 pF 50 V C0G  [C_0402_1005Metric]
C70  10 pF 50 V C0G  [C_0402_1005Metric]
D5  5 V bidirectional 0.2 pF RF ESD
J10  U.FL-R-SMT-1(60)
R63  100 kOhm 1%  [R_0402_1005Metric]
R64  100 kOhm 1%  [R_0402_1005Metric]
R65  100 kOhm 1%  [R_0402_1005Metric]
R66  100 kOhm 1%  [R_0402_1005Metric]
R67  10 kOhm 1%  [R_0402_1005Metric]
R68  10 kOhm 1%  [R_0402_1005Metric]
R69  22 Ohm 1%  [R_0402_1005Metric]
R70  22 Ohm 1%  [R_0402_1005Metric]
R71  22 Ohm 1%  [R_0402_1005Metric]
R72  22 Ohm 1%  [R_0402_1005Metric]
R73  0 Ohm  [R_0402_1005Metric]
U10  E22-900M22S

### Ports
3V3_DIGITAL, GND_DIGITAL, LORA_BUSY, LORA_DIO1, LORA_MISO_U1, LORA_MOSI_U1, LORA_NSS_U1, LORA_RESET_N, LORA_RXEN, LORA_SCK_U1, LORA_TXEN

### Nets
3V3_DIGITAL: C66.1 C67.1 R67.1 R68.1 U10.9(VCC) ; port 3V3_DIGITAL
GND_DIGITAL: C66.2 C67.2 C68.2 C69.2 C70.2 D5.2 J10.SHIELD(SHELL) R63.2 R64.2 R65.2 R66.2 U10.1(GND) U10.2(GND) U10.3(GND) U10.4(GND) U10.5(GND) U10.10(GND) U10.11(GND) U10.12(GND) U10.20(GND) U10.22(GND) ; port GND_DIGITAL
LORA_BUSY: R66.1 U10.14(BUSY) ; port LORA_BUSY
LORA_DIO1: R65.1 U10.13(DIO1) ; port LORA_DIO1
LORA_MISO_U1: R72.2 ; port LORA_MISO_U1
LORA_MISO_U10: R72.1 U10.16(MISO)
LORA_MOSI_U1: R71.1 ; port LORA_MOSI_U1
LORA_MOSI_U10: R71.2 U10.17(MOSI)
LORA_NSS_U1: R69.1 ; port LORA_NSS_U1
LORA_NSS_U10: R68.2 R69.2 U10.19(NSS)
LORA_RESET_N: C68.1 R67.2 U10.15(NRST) ; port LORA_RESET_N
LORA_RF_ANT: C70.1 D5.1 J10.1(SIGNAL) R73.2
LORA_RF_MODULE: C69.1 R73.1 U10.21(ANT)
LORA_RXEN: R64.1 U10.6(RXEN) ; port LORA_RXEN
LORA_SCK_U1: R70.1 ; port LORA_SCK_U1
LORA_SCK_U10: R70.2 U10.18(SCK)
LORA_TXEN: R63.1 U10.7(TXEN) ; port LORA_TXEN

Not connected (* = marked no-connect by the designer): U10 8(DIO2)*

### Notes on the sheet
- Every connected symbol pin has one explicit wire stub. Only hierarchical labels cross functional-sheet boundaries.

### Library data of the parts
C66 = C66_GRM155R71E104KE14D: Manufacturer: Murata; Population: FITTED; Authority: Ebyte_E22-M_v1.2
C67 = C67_GRM188R61A106KE69D: Manufacturer: Murata; Population: FITTED; Authority: Ebyte_E22-M_v1.2
C68 = C68_GRM155R71E104KE14D: Manufacturer: Murata; Population: FITTED; Authority: Ebyte_E22-M_v1.2
C69 = C69_GRM1555C1H100JA01D: Manufacturer: Murata; Population: DNP; Authority: Ebyte_E22-M_v1.2
C70 = C70_GRM1555C1H100JA01D: Manufacturer: Murata; Population: DNP; Authority: Ebyte_E22-M_v1.2
D5 = D5_PESD5V0C1BSF: Manufacturer: Nexperia; Population: FITTED; Authority: Nexperia_PESD5V0C1BSF_v3
J10 = J10_U.FL-R-SMT-1_60: Manufacturer: CONTROLLED_AUTHORITY; Population: FITTED; Authority: PCB_MAIN_LORA_PIN_AUTHORITY_REV_A.csv;PCB_MAIN_CONNECTOR_FIXTURE_PIN_AUTHORITY_REV_A.csv
R63 = R63_ERJ-2RKF1003X: Manufacturer: Panasonic; Population: FITTED; Authority: Ebyte_E22-M_v1.2
R64 = R64_ERJ-2RKF1003X: Manufacturer: Panasonic; Population: FITTED; Authority: Ebyte_E22-M_v1.2
R65 = R65_ERJ-2RKF1003X: Manufacturer: Panasonic; Population: FITTED; Authority: Ebyte_E22-M_v1.2
R66 = R66_ERJ-2RKF1003X: Manufacturer: Panasonic; Population: FITTED; Authority: Ebyte_E22-M_v1.2
R67 = R67_ERJ-2RKF1002X: Manufacturer: Panasonic; Population: FITTED; Authority: Ebyte_E22-M_v1.2
R68 = R68_ERJ-2RKF1002X: Manufacturer: Panasonic; Population: FITTED; Authority: Ebyte_E22-M_v1.2
R69 = R69_ERJ-2RKF22R0X: Manufacturer: Panasonic; Population: FITTED; Authority: Ebyte_E22-M_v1.2
R70 = R70_ERJ-2RKF22R0X: Manufacturer: Panasonic; Population: FITTED; Authority: Ebyte_E22-M_v1.2
R71 = R71_ERJ-2RKF22R0X: Manufacturer: Panasonic; Population: FITTED; Authority: Ebyte_E22-M_v1.2
R72 = R72_ERJ-2RKF22R0X: Manufacturer: Panasonic; Population: FITTED; Authority: Ebyte_E22-M_v1.2
R73 = R73_ERJ-2GE0R00X: Manufacturer: Panasonic; Population: FITTED; Authority: Ebyte_E22-M_v1.2
U10 = U10_E22-900M22S: Manufacturer: Ebyte; Population: FITTED; Authority: PCB_MAIN_LORA_PIN_AUTHORITY_REV_A.csv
